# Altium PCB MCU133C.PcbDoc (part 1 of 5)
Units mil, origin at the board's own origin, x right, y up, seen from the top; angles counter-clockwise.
Board outline 2300 x 5500 mil, 4 copper layers (Top Signal, GND, PWR, Bottom Signal), stack 61.6 mil thick; 278 components, 226 nets, 1057 pads, 868 vias.
Unrouted connection lines stored in the file: 237.
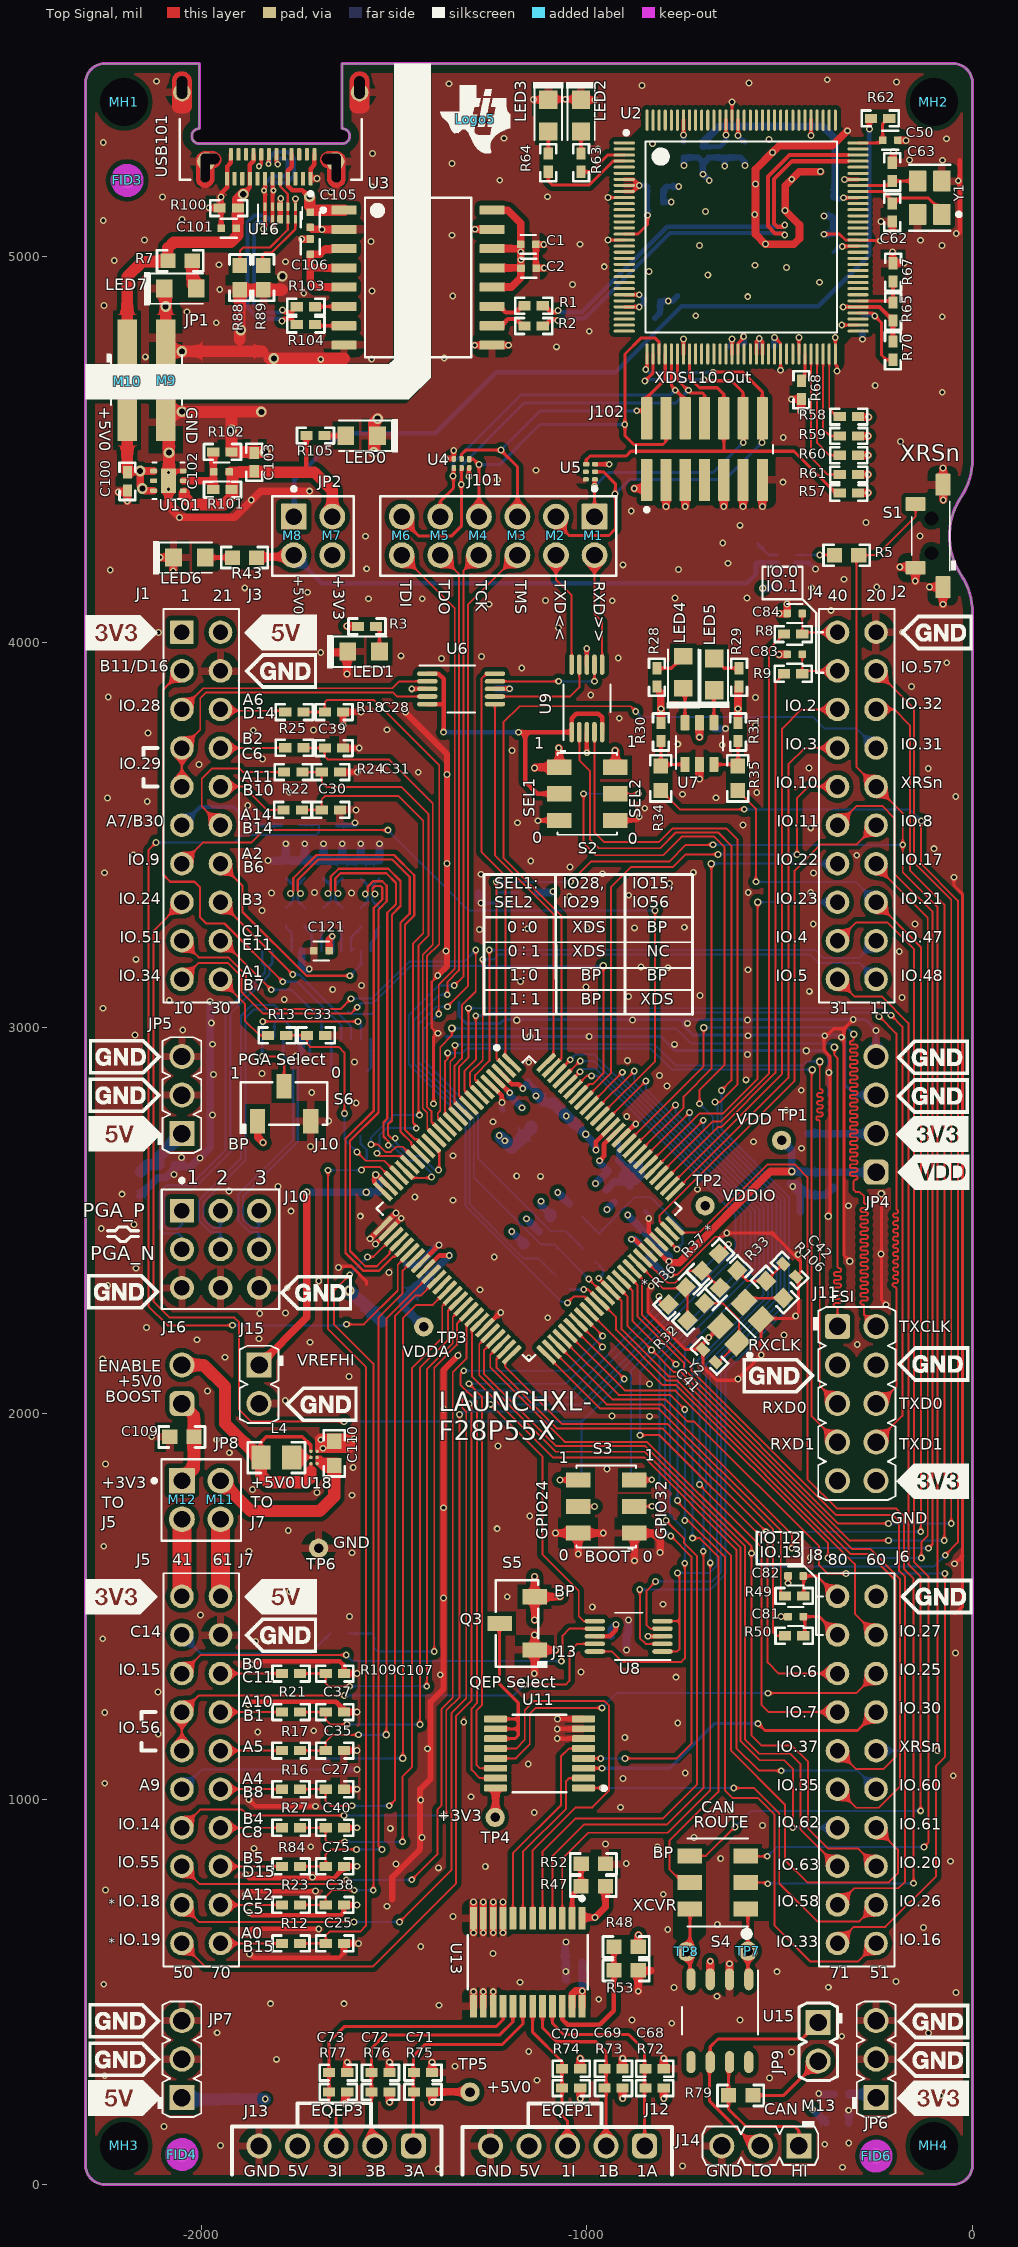
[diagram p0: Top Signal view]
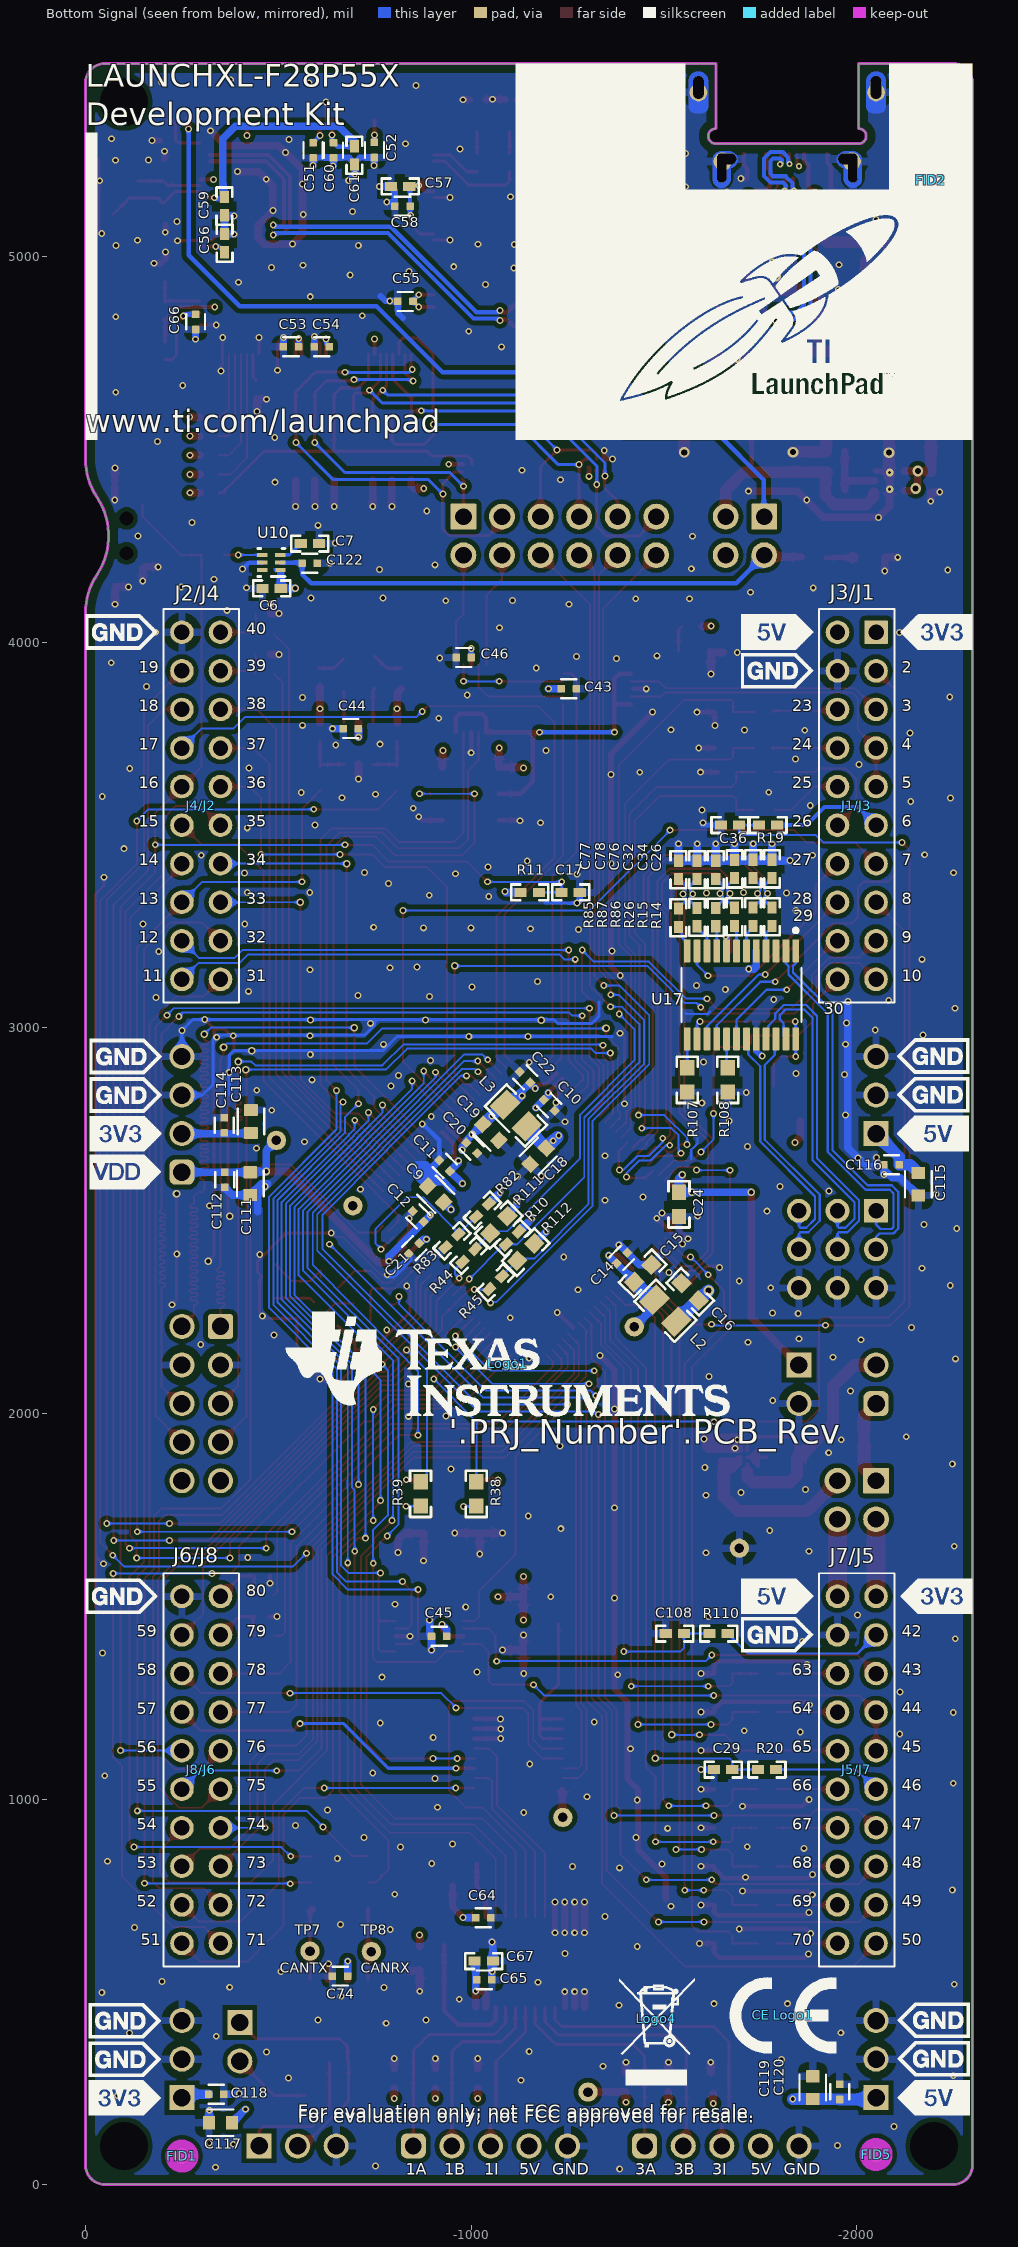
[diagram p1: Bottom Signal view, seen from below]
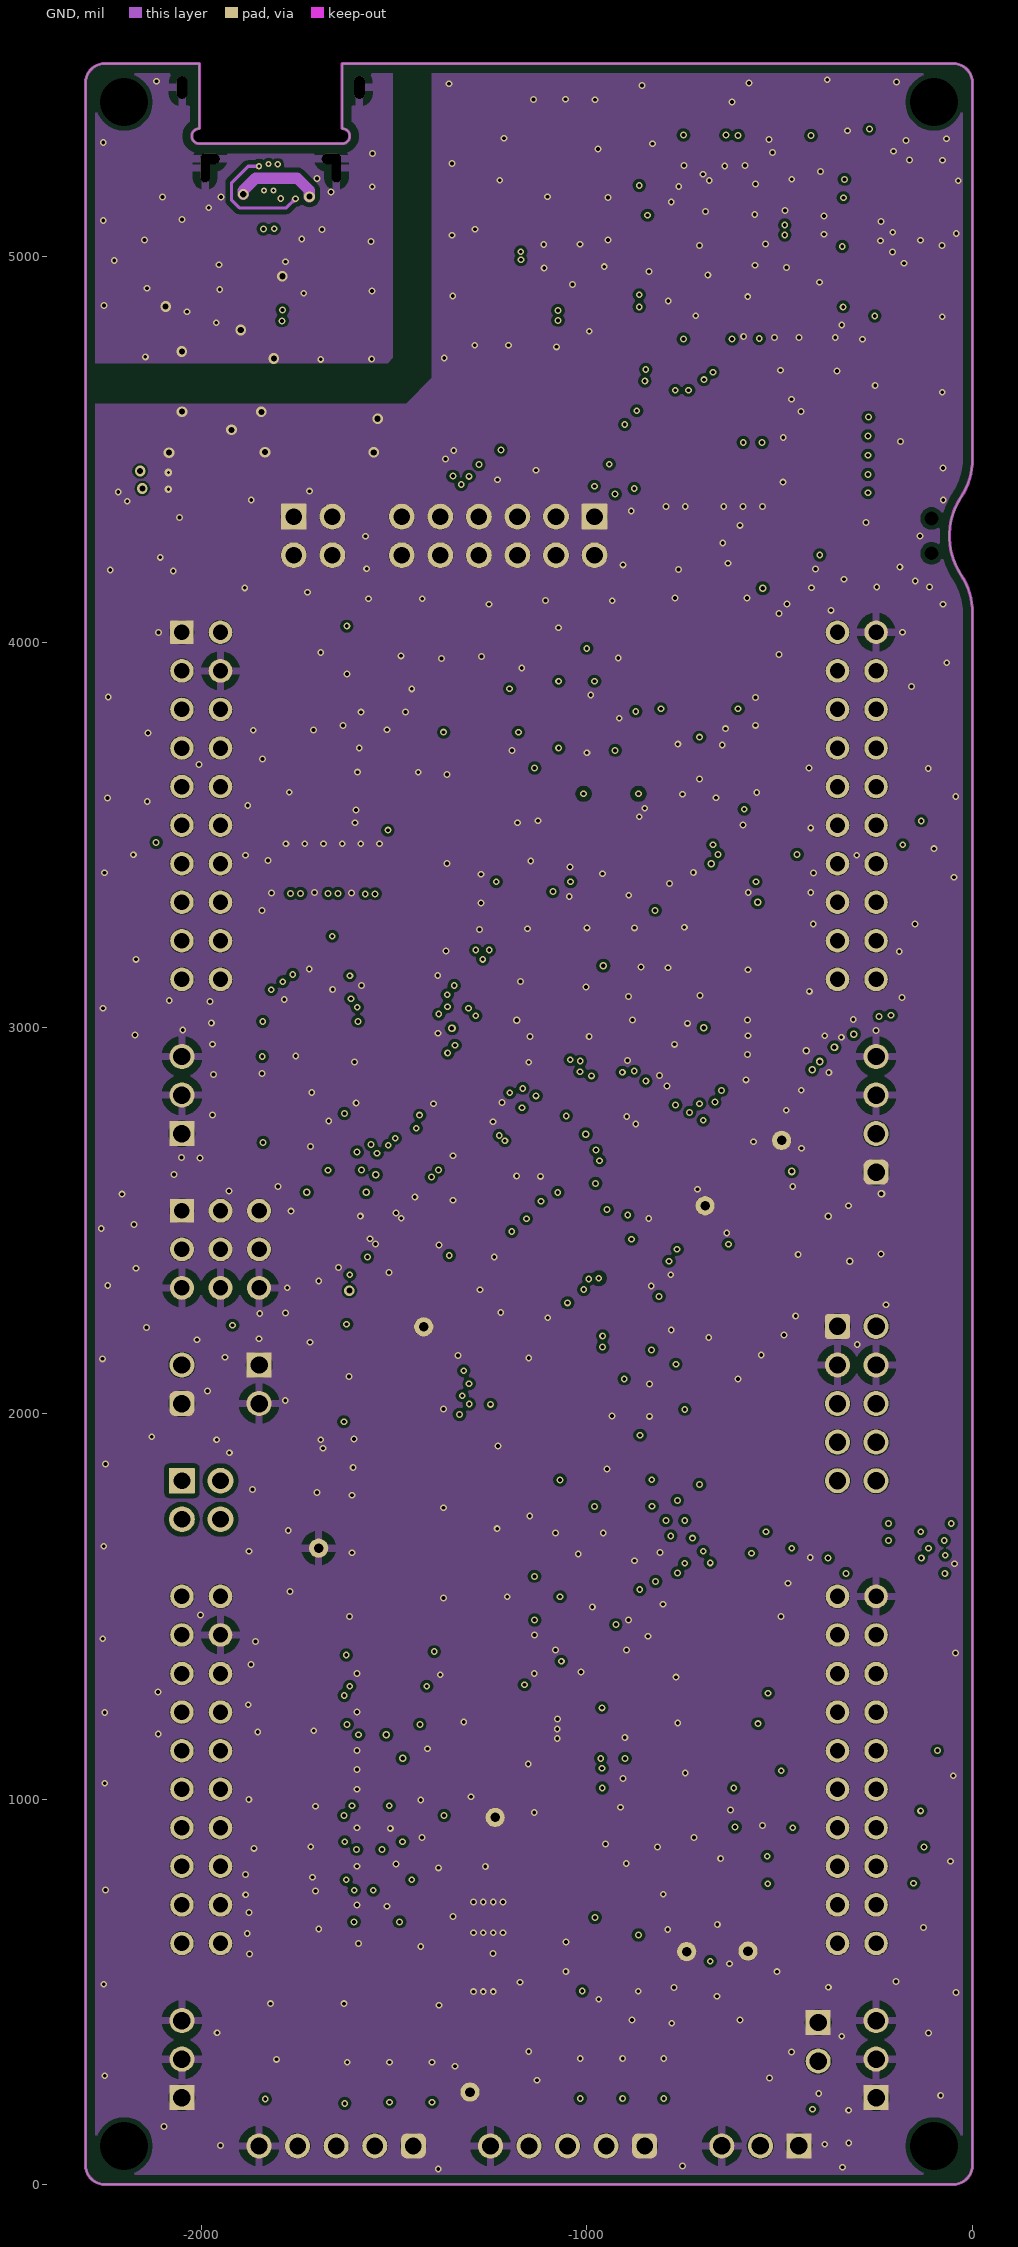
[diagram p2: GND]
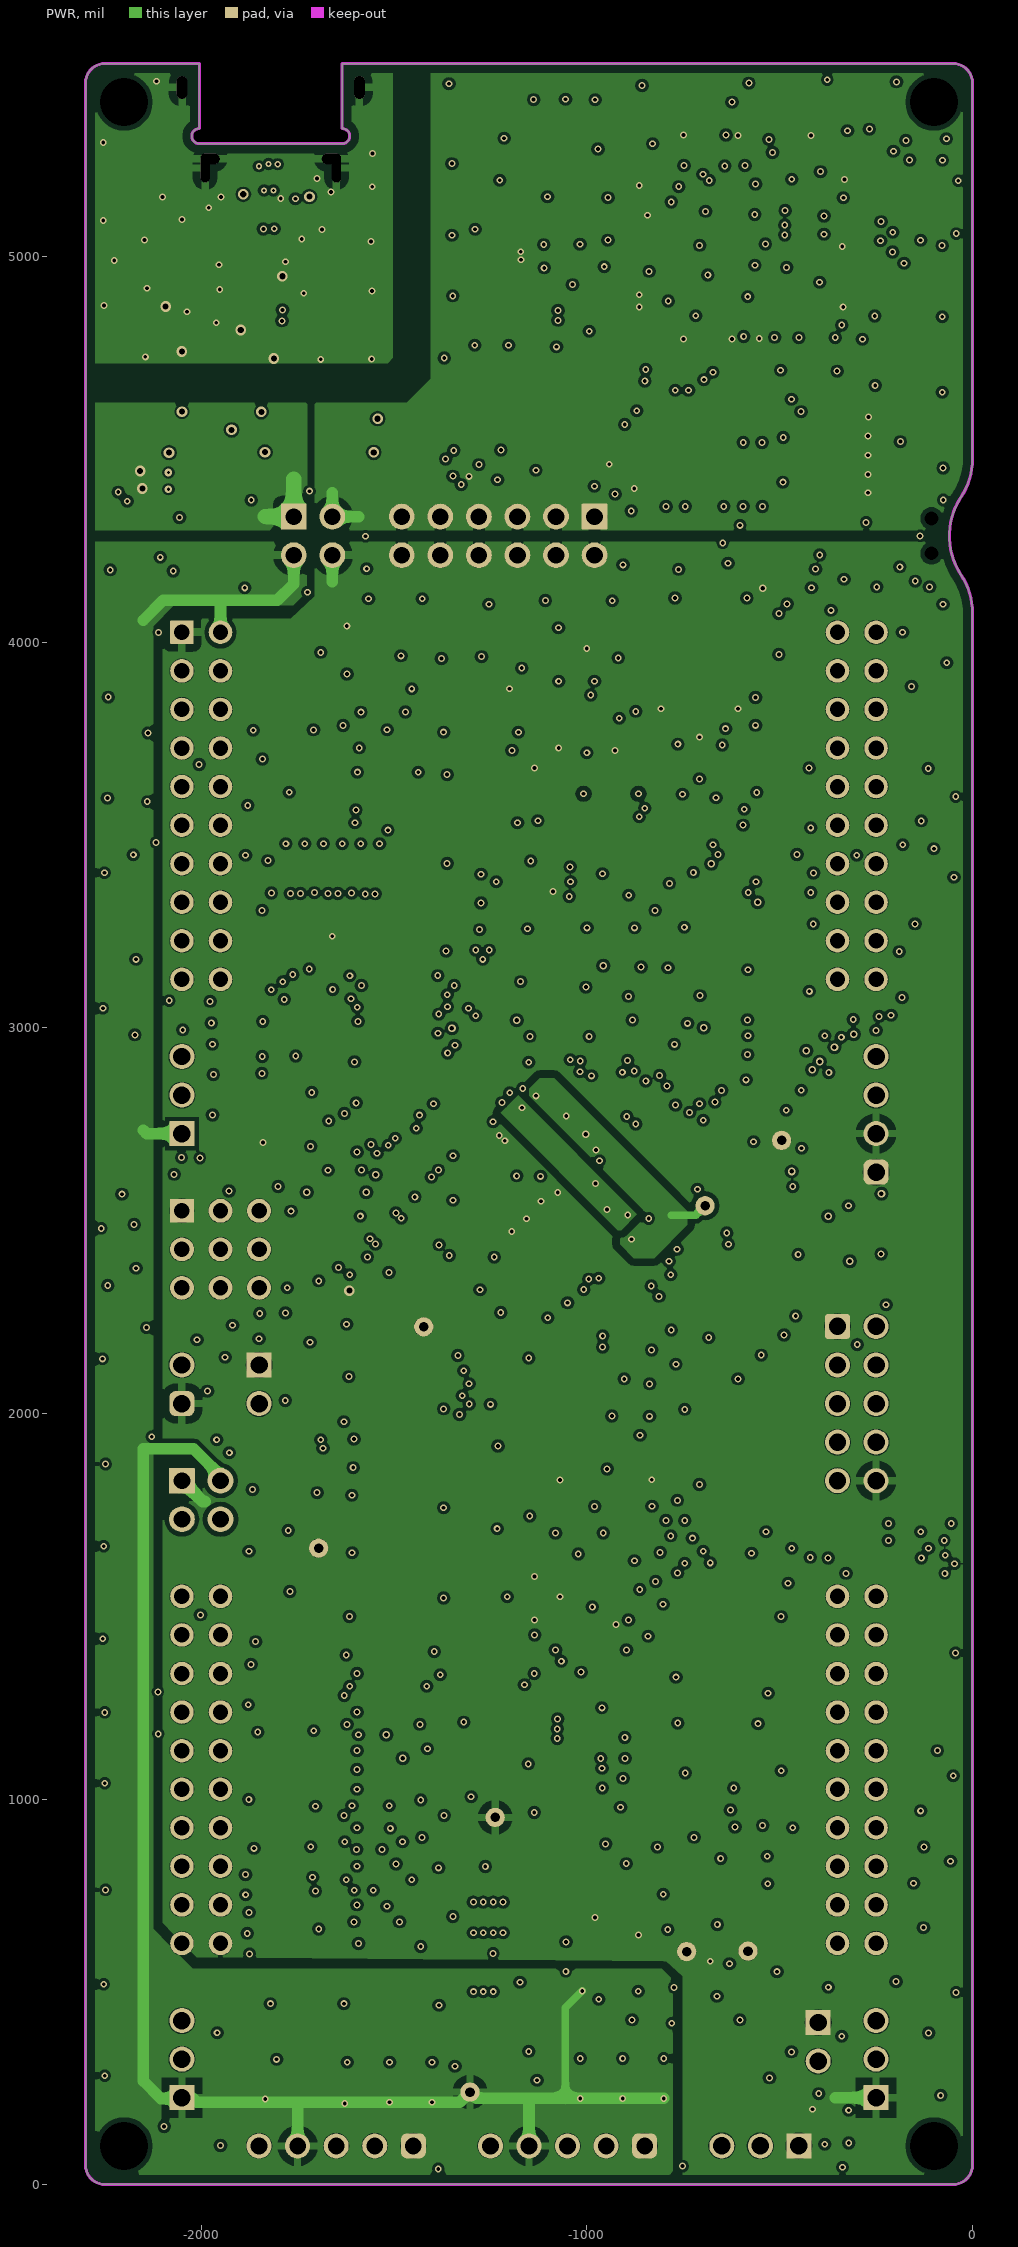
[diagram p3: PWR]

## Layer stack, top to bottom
Top Solder: solder mask 0.4, Solder Resist, Dk 3.5
Top Signal: signal copper 1.4
Dielectric 1: prepreg 8, FR-4, Dk 4.2
GND: signal copper 1.4
Dielectric 2: core 40, FR-4, Dk 4.2
PWR: signal copper 1.4
Dielectric 3: prepreg 8, FR-4, Dk 4.2
Bottom Signal: signal copper 1.4
Bottom Solder: solder mask 0.4, Solder Resist, Dk 3.5

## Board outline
-2250.04,0.55 cw(c-2250.04,50.55) -2300.04,50.55 -2300.04,5450.55 cw(c-2250.04,5450.55) -2250.04,5500.55 -2004.76,5500.55 -2004.76,5332.05 ccw(c-2004.76,5312.36) -2024.45,5312.36 ccw(c-2004.76,5312.36) -2004.76,5292.68 -1634.68,5292.68 ccw(c-1634.68,5312.36) -1615,5312.36 ccw(c-1634.68,5312.36) -1634.68,5332.05 -1634.68,5500.55 -50.04,5500.55 cw(c-50.04,5450.55) -0.04,5450.55 -0.04,4475.55 cw(c-181.7,4475.55) -30.04,4375.55 ccw(c121.63,4275.55) -30.04,4175.55 cw(c-181.7,4075.55) -0.04,4075.55 -0.04,50.55 cw(c-50.04,50.55) -50.04,0.55

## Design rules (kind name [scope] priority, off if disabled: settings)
AcuteAngle [All] p1: minimum=4.50000000000000E+0001 checktracksonly=TRUE
AssemblyTestPointUsage [All] p1: valid=2
BoardOutlineClearance BoardOutlineClearance_MountingHoles [OnCopper and InComponentClass('Mounting Holes')] p1: gap=40 ignorepadtopadclearanceinfootprint=FALSE
BoardOutlineClearance BoardOutlineClearance_Poly [OnCopper and IsPoly] p2: gap=25 ignorepadtopadclearanceinfootprint=FALSE
BoardOutlineClearance BoardOutlineClearance_USB101 [InComponent('USB101')] p3: gap=0 ignorepadtopadclearanceinfootprint=FALSE
BoardOutlineClearance [OnCopper and Not InComponentClass('Logo') and not InComponentClass('FiducialMark') and not InRegion(1000,500,4000,800) and not InPoly] p4: gap=10 ignorepadtopadclearanceinfootprint=FALSE
Clearance USB101 [InComponent('USB101') vs OnLayer('Keep-Out Layer')] p1: gap=7.87 ignorepadtopadclearanceinfootprint=FALSE
Clearance Clearance_1 [inpolygon vs inpolygon] p2: gap=19.68 ignorepadtopadclearanceinfootprint=FALSE
Clearance ISVIA [ISVIA vs ISVIA] p3: gap=7.87 ignorepadtopadclearanceinfootprint=FALSE
Clearance Clearance_FiducialMark [InComponentClass('FiducialMark') vs InComponentClass('FiducialMark')] p4: gap=0 ignorepadtopadclearanceinfootprint=FALSE
Clearance Clearance_Boardedge [All vs IsKeepOut] p5: gap=11.81 ignorepadtopadclearanceinfootprint=FALSE
Clearance INPOLYGON [InPolygon] p6: gap=11.81 ignorepadtopadclearanceinfootprint=FALSE
Clearance [All] p7: gap=5.91 ignorepadtopadclearanceinfootprint=FALSE
ComponentClearance ComponentClearance_THtoTH_1 [All vs InComponentClass('Shunt')] p1: gap=0 collisioncheckmode=3 verticalgap=0 showdistances=FALSE
ComponentClearance "ComponentClearance_overlay to overlay" [OnBottomSilkscreen vs OnTopSilkscreen] p2: gap=0 collisioncheckmode=3 verticalgap=0 showdistances=FALSE
ComponentClearance ComponentClearance_MountingHoles_FiducialMarks [InComponentClass('Mounting Holes') vs InComponentClass('FiducialMark')] p3: gap=50 collisioncheckmode=3 verticalgap=10 showdistances=FALSE
ComponentClearance ComponentClearance_Shunt [InComponentClass('Header') vs InComponentClass('Shunt')] p4: gap=0 collisioncheckmode=3 verticalgap=0 showdistances=FALSE
ComponentClearance ComponentClearance_Logo [InComponentClass('Logo')] p5: gap=0 collisioncheckmode=3 verticalgap=0 showdistances=FALSE
ComponentClearance ComponentClearance_Logo_1 [InComponentClass('Logo') vs InComponentClass('Logo')] p6: gap=0 collisioncheckmode=3 verticalgap=0 showdistances=FALSE
ComponentClearance ComponentClearance_ScrewToNut [(HasFootprint('NY PMS 440 0025 PH')) vs (HasFootprint('Keystone_1902C'))] p7: gap=3.94 collisioncheckmode=3 verticalgap=3.94 showdistances=FALSE
ComponentClearance ComponentClearance_MountingHoles [InComponentClass('Mounting Holes')] p8: gap=250 collisioncheckmode=3 verticalgap=100000 showdistances=FALSE
ComponentClearance ComponentClearance_SmallPassives [HasFootprint('0201*') or HasFootprint('0402*') or HasFootprint('0508') or HasFootprint('0603*') or HasFootprint('0612') or HasFootprint('0805*') or HasFootprint('0815*') or HasFootprint('0830*') or HasFootprint('1206*') or HasFootprint('1210*') or HasFootprint('1808*') or HasFootprint('1812*') or HasFootprint('1825*') or HasFootprint('2010*') or HasFootprint('2220*') or HasFootprint('2225*') or HasFootprint('2512*') or HasFootprint('2728*') or HasFootprint('3518*') vs HasFootprint('0201*') or HasFootprint('0402*') or HasFootprint('0508') or HasFootprint('0603*') or HasFootprint('0612') or HasFootprint('0805*') or HasFootprint('0815*') or HasFootprint('0830*') or HasFootprint('1206*') or HasFootprint('1210*') or HasFootprint('1808*') or HasFootprint('1812*') or HasFootprint('1825*') or HasFootprint('2010*') or HasFootprint('2220*') or HasFootprint('2225*') or HasFootprint('2512*') or HasFootprint('2728*') or HasFootprint('3518*')] p9: gap=10 collisioncheckmode=3 verticalgap=0 showdistances=FALSE
ComponentClearance ComponentClearance_THtoSMT [IsThruComponent vs IsSMTComponent] p10: gap=10 collisioncheckmode=3 verticalgap=10 showdistances=FALSE
ComponentClearance ComponentClearance_THtoTH [IsThruComponent vs IsThruComponent] p11: gap=20 collisioncheckmode=3 verticalgap=30 showdistances=FALSE
DiffPairsRouting [All] p1: maxlimit=100 minlimit=5.91 mostfreqgap=5.91 toplayer_minwidth=5.91 toplayer_maxwidth=15 toplayer_prefwidth=10.63 midlayer1_minwidth=5.91 midlayer1_maxwidth=15 midlayer1_prefwidth=10.63 midlayer2_minwidth=5.91 midlayer2_maxwidth=15 midlayer2_prefwidth=10.63 bottomlayer_minwidth=5.91 bottomlayer_maxwidth=15 bottomlayer_prefwidth=10.63 maxuncoupledlength=1000
FabricationTestPointUsage TestPointUsage [All] p1: valid=2 allowmultiple=FALSE
FabricationTestpoint Testpoint [All] p1: side=3 testpointundercomponent=TRUE minsize=40 maxsize=100 preferedsize=60 minholesize=0 maxholesize=40 preferedholesize=32 testpointgrid=1 allowsidetop=TRUE allowsidebottom=TRUE usegrid=TRUE gridtolerance=0.01
FanoutControl Fanout_LCC [IsLCC] p1: bgadir=Out bgaviamode=Centered fanoutstyle=Auto fanoutdirection=Alternating viagrid=1 // Fanout_LCC (Default Rule)
FanoutControl Fanout_BGA [IsBGA] p2: bgadir=Out bgaviamode=Centered fanoutstyle=Auto fanoutdirection=Alternating viagrid=1 // Fanout_BGA (Default Rule)
FanoutControl Fanout_Default [All] p4: bgadir=Out bgaviamode=Centered fanoutstyle=Auto fanoutdirection=Alternating viagrid=1 // Fanout_Default (Default Rule)
FanoutControl Fanout_Small [(CompPinCount < 5)] p5: bgadir=Out bgaviamode=Centered fanoutstyle=Auto fanoutdirection=OutThenIn viagrid=1 // Fanout_Small (Default Rule)
HoleSize [All] p1: absolutevalues=TRUE maxlimit=251 minlimit=7.87 maxpercent=80.000 minpercent=20.000
HoleToHoleClearance HoleToHoleClearance_USB101 [InComponent('USB101') vs InComponent('USB101')] p1: gap=0 allowstackedmicrovias=TRUE
HoleToHoleClearance [All] p2: gap=9.84 allowstackedmicrovias=TRUE
MatchedLengths FSIRX [InNetClass('FSIRX')] p1: tolerance=25 checknetsindiffpair=FALSE checkdiffpairvsdiffpair=TRUE checkxsignals=TRUE checkothers=TRUE
MatchedLengths FSITX [InNetClass('FSITX')] p2: tolerance=25 checknetsindiffpair=FALSE checkdiffpairvsdiffpair=TRUE checkxsignals=TRUE checkothers=TRUE
MinimumAnnularRing MinimumAnnularRing_1 [InComponent('USB101')] p1: minimumring=0
MinimumAnnularRing [All] p2: minimumring=3.94
MinimumAnnularRing MinimumAnnularRing_ThermalPadVias [IsVia and InAnyComponent] p3: minimumring=3.94
MinimumSolderMaskSliver MinimumSolderMaskSliver_Logo [InComponentClass('Logo') vs InComponentClass('Logo')] p1: minsoldermaskwidth=0.7
MinimumSolderMaskSliver [All] p2: minsoldermaskwidth=3
PlaneClearance [All] p1: clearance=5
PlaneConnect [All] p1: planeconnectstyle=Relief reliefexpansion=10 reliefentries=4 reliefconductorwidth=25 reliefairgap=10
PolygonConnect PolygonConnect_via [isvia] p1: connectstyle=Direct reliefconductorwidth=10 reliefentries=4 polygonreliefangle="90 Angle" airgapwidth=5
PolygonConnect [All] p2: connectstyle=Relief reliefconductorwidth=20 reliefentries=4 polygonreliefangle="90 Angle" airgapwidth=19.68
RoutingVias ThermalPadVias [IsVia and InAnyComponent] p1: holewidth=7.87 width=19.68 viastyle="Through Hole" minholewidth=7.87 minwidth=19.68 maxholewidth=12.99 maxwidth=23.62
RoutingVias [All] p2: holewidth=9.84 width=17.72 viastyle="Through Hole" minholewidth=7.87 minwidth=15.75 maxholewidth=40 maxwidth=65
SilkToBoardRegionClearance [Not ((IsComment or IsDesignator) And (Hide <> 'False')) and not InRegion(1000,500,4000,800)] p1:
SilkToSilkClearance SilkToSilkClearance_Pb-FreeLogo [(HasFootprint('Pb-Free_Overlay_Medium') OR HasFootprint('Pb-Free_Overlay_Small')) vs (HasFootprint('Pb-Free_Overlay_Medium') OR HasFootprint('Pb-Free_Overlay_Small'))] p1: silktosilkclearance=0
SilkToSilkClearance [All] p2: silktosilkclearance=3
SilkToSolderMaskClearance SilkToComponentPadClearance [(IsPad or IsFill or IsRegion) and InAnycomponent] p1: minsilkscreentomaskgap=3 clearancetoexposedcopper=TRUE
SilkToSolderMaskClearance "Silk to Solder Mask Opening" [(IsPad or IsFIll or IsRegion) and InAnyComponent] p2: minsilkscreentomaskgap=3 clearancetoexposedcopper=TRUE
SolderMaskExpansion SolderMaskExpansion_1 [All] p1: expansion=4 istentingtop=FALSE
SolderMaskExpansion SolderMaskExpansion_Via [IsVia] p2: expansion=2 istentingtop=FALSE
Width Analog [InNetClass('Analog')] p1: maxlimit=25 minlimit=8 preferedwidth=8
Width [All] p2: maxlimit=100 minlimit=5 preferedwidth=5 checkconnectedcopper=TRUE
13 further rules are at their usual default settings.

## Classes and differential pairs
component class MCU133C_F28P55x_Device: C9 C10 C11 C12 C14 C15 C16 C17 C18 C19 C20 C21 C22 L2 L3 R10 R11 R44 R45 R82 R83 R111 R112 S1
net class FSITX: GPIO44_FSITXCLK GPIO49_FSITXD0 GPIO50_FSITXD1
net class FSIRX: GPIO52_FSIRXD0 GPIO53_FSIRXD1 GPIO54_FSIRXCLK
component class MCU133C_USB_and_Power: C1 C2 C6 C7 C100 C101 C102 C103 C105 C106 C109 C110 C111 C112 C113 C114 C115 C116 C117 C118 C119 C120 C122 J16 JP1 JP2 JP4 JP5 JP6 JP7 JP10 L4 LED0 LED1 LED6 LED7 R1 R2 R3 R5 R7 R43 R88 R89 R100 R101 R102 R103 R104 R105 TP1 TP2 TP3 TP4 TP5 TP6 U3 U10 U16 U18 U101 USB101
component class MCU133C_XDS110_MCU: 45mil C50 C51 C52 C53 C54 C55 C56 C57 C58 C59 C60 C61 C62 C63 C66 J101 J102 LED2 LED3 R57 R58 R59 R60 R61 R62 R63 R64 R65 R67 R68 R70 R? U2 U4 U5 Y1
component class MCU133C_ADC: C24 C25 C26 C27 C28 C29 C30 C31 C32 C33 C34 C35 C36 C37 C38 C39 C40 C75 C76 C77 C78 C107 C108 J15 R12 R13 R14 R15 R16 R17 R18 R19 R20 R21 R22 R23 R24 R25 R26 R27 R84 R85 R86 R87 R109 R110 U1
component class MCU133C_Connectors: C68 C69 C70 C71 C72 C73 C74 C81 C82 C83 C84 J1/J3 J4/J2 J5/J7 J8/J6 J10 J11 J12 J13 J14 JP8 JP9 R8 R9 R49 R50 R72 R73 R74 R75 R76 R77 R79 TP7 TP8 U15
component class MCU133C_AltRouting_Misc: C41 C42 C43 C44 C45 C46 C64 C65 C67 C121 LED4 LED5 R28 R29 R30 R31 R32 R33 R34 R35 R36 R37 R38 R39 R47 R48 R52 R53 R106 R107 R108 S2 S3 S4 S5 S6 U6 U7 U8 U9 U11 U13 U17 Y2
component class Header: J11 J12 J13 J14 J15 J16 JP1 JP4 JP5 JP6 JP7 JP9 JP10
component class AssemblyNote: ZZ1 ZZ2 ZZ3
component class FiducialMark: FID1 FID2 FID3 FID4 FID5 FID6
component class MCU133C_Hardware: "CE Logo1" FID1 FID2 FID3 FID4 FID5 FID6 Logo1 Logo3 Logo4 Logo5 M1 M2 M3 M4 M5 M6 M7 M8 M9 M10 M11 M12 M13 MH1 MH2 MH3 MH4 ZZ1 ZZ2 ZZ3
component class Logo: Logo1 Logo5
component class Shunt: M1 M2 M3 M4 M5 M6 M7 M8 M9 M10 M11 M12 M13
differential pair XDS_D: +XDS_D_P -XDS_D_N
differential pair USB_D: +USB_D_P -USB_D_N
differential pair PGA3_IN: +PGA3_IN_P -PGA3_IN_N
differential pair PGA2_IN: +PGA2_IN_P -PGA2_IN_N
differential pair PGA1_IN: +PGA1_IN_P -PGA1_IN_N
differential pair MCU_PGA3_IN: +MCU_PGA3_IN_P -MCU_PGA3_IN_N
differential pair MCU_PGA2_IN: +MCU_PGA2_IN_P -MCU_PGA2_IN_N
differential pair MCU_PGA1_IN: +MCU_PGA1_IN_P -MCU_PGA1_IN_N
differential pair ADCINPGA3_IN: +ADCINPGA3_IN_P -ADCINPGA3_IN_N
differential pair ADCINPGA2_IN: +ADCINPGA2_IN_P -ADCINPGA2_IN_N
differential pair ADCINPGA1_IN: +ADCINPGA1_IN_P -ADCINPGA1_IN_N

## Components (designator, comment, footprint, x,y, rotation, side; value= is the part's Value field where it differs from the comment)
C1 "885012205018" FP-885012205018_0402-MFG -1152.04,5031.55 r180 top value=100nF
C2 "885012205018" FP-885012205018_0402-MFG -1151.02,4969.92 r180 top value=100nF
C6 "885012205037" 0402 -482.76,4139.55 r0 bottom value=0.1uF
C7 "885012205037" 0402 -581.66,4255.55 r180 bottom value=0.1uF
C9 "CC0603KRX5R6BB106" FP-CC0603KRX5R6BB106_0603-MFG -907.86,2568.67 r225 bottom value=10µF
C10 "885012205018" FP-885012205018_0402-MFG -1202.71,2799.05 r45 bottom value=100nF
C11 "885012205018" FP-885012205018_0402-MFG -931.24,2642.53 r225 bottom value=100nF
C12 "885012205018" FP-885012205018_0402-MFG -862.62,2510.8 r225 bottom value=100nF
C14 "885012205018" FP-885012205018_0402-MFG -1391.08,2403 r315 bottom value=100nF
C15 "CGA3E3X5R1A225K080AB" 0603 -1445.2,2363.22 r135 bottom value=2.2uF
C16 "CGA3E3X5R1A225K080AB" 0603 -1567.88,2315.53 r45 bottom value=2.2uF
C17 "885012205037" 0402 -1258.04,3350.95 r180 bottom value=0.1uF
C18 "CC0603KRX5R6BB106" FP-CC0603KRX5R6BB106_0603-MFG -1173.78,2667.08 r135 bottom value=10µF
C19 "CC0603KRX5R6BB106" FP-CC0603KRX5R6BB106_0603-MFG -1051.11,2729.05 r45 bottom value=10µF
C20 "885012205018" FP-885012205018_0402-MFG -1001.61,2688.55 r45 bottom value=100nF
C21 "885012205018" FP-885012205018_0402-MFG -852.04,2427.95 r135 bottom value=100nF
C22 "885012205018" FP-885012205018_0402-MFG -1139.8,2871.97 r225 bottom value=100nF
C24 "CGA3E3X5R1A225K080AB" 0603 -1539.04,2542.09 r270 bottom value=2.2uF
C25 "GRM1555C1H331JA01D" 0402 -1653.66,625.55 r0 top value=330pF
C26 "GRM1555C1H331JA01D" 0402 -1779.95,3412.05 r90 bottom value=330pF
C27 "GRM1555C1H331JA01D" 0402 -1653.66,1025.55 r0 top value=330pF
C28 "GRM1555C1H331JA01D" 0402 -1655.67,3818.85 r0 top value=330pF
C29 "GRM1555C1H331JA01D" 0402 -1653.66,1076.55 r0 bottom value=330pF
C30 "GRM1555C1H331JA01D" 0402 -1663.82,3564.92 r0 top value=330pF
C31 "GRM1555C1H331JA01D" 0402 -1663.82,3662.93 r0 top value=330pF
C32 "GRM1555C1H331JA01D" 0402 -1683.26,3411.97 r90 bottom value=330pF
C33 "GRM1555C1H331JA01D" 0402 -1702.04,2980.24 r0 top value=330pF
C34 "GRM1555C1H331JA01D" 0402 -1731.34,3412.14 r90 bottom value=330pF
C35 "GRM1555C1H331JA01D" 0402 -1653.66,1125.55 r0 top value=330pF
C36 "GRM1555C1H331JA01D" 0402 -1671.42,3525.55 r0 bottom value=330pF
C37 "GRM1555C1H331JA01D" 0402 -1653.66,1225.55 r0 top value=330pF
C38 "GRM1555C1H331JA01D" 0402 -1653.66,725.55 r0 top value=330pF
C39 "GRM1555C1H331JA01D" 0402 -1655.75,3725.55 r0 top value=330pF
C40 "GRM1555C1H331JA01D" 0402 -1653.66,925.55 r0 top value=330pF
C41 "C0402C120J3GACAUTO" 0402 -682.4,2149.43 r135 top value=12pF
C42 "C0402C120J3GACAUTO" 0402 -474.04,2371.03 r315 top value=12pF
C43 "885012205018" FP-885012205018_0402-MFG -1253.39,3879.33 r180 bottom value=100nF
C44 "885012205018" FP-885012205018_0402-MFG -688.04,3776.02 r180 bottom value=100nF
C45 "885012205018" FP-885012205018_0402-MFG -916.78,1422.07 r0 bottom value=100nF
C46 "885012205018" FP-885012205018_0402-MFG -980.59,3960.28 r180 bottom value=100nF
C50 "885012205050" FP-885012205050_0402-MFG -213.15,5301.77 r180 top value=10nF
C51 "885012205050" FP-885012205050_0402-MFG -590.04,5275.55 r90 bottom value=10nF
C52 "885012205050" FP-885012205050_0402-MFG -749.25,5276.46 r90 bottom value=10nF
C53 "885012205050" FP-885012205050_0402-MFG -532.76,4765.83 r180 bottom value=10nF
C54 "885012205018" FP-885012205018_0402-MFG -612.68,4765.83 r180 bottom value=100nF
C55 "885012205018" FP-885012205018_0402-MFG -829.61,4883.66 r180 bottom value=100nF
C56 "885012105012" 0402 -360.83,5034.69 r90 bottom value=1uF
C57 "885012105012" 0402 -816.06,5181.97 r0 bottom value=1uF
C58 "885012205050" FP-885012205050_0402-MFG -822.04,5130.55 r180 bottom value=10nF
C59 "885012105012" 0402 -360,5130.83 r270 bottom value=1uF
C60 "885012205018" FP-885012205018_0402-MFG -643.19,5275.47 r90 bottom value=100nF
C61 "885012105012" 0402 -697.43,5262.48 r270 bottom value=1uF
C62 "CL05C120JB5NNNC" 0402 -207.94,5114.17 r270 top value=12pF
C63 "CL05C120JB5NNNC" 0402 -207.94,5219.53 r90 top value=12pF
C64 "885012205018" FP-885012205018_0402-MFG -1031.5,692.05 r180 bottom value=100nF
C65 "885012205018" FP-885012205018_0402-MFG -1034.29,531.06 r0 bottom value=100nF
C66 "885012205018" FP-885012205018_0402-MFG -285.51,4830.59 r90 bottom value=100nF
C67 "885012205061" 0402 -1032.64,579.72 r180 bottom value=1000pF
C68 "885012205061" 0402 -824.06,300.55 r0 top value=1000pF
C69 "885012205061" 0402 -930.79,300.55 r0 top value=1000pF
C70 "885012205061" 0402 -1040.79,300.55 r0 top value=1000pF
C71 "885012205061" 0402 -1425.04,290.55 r0 top value=1000pF
C72 "885012205061" 0402 -1535.04,290.55 r0 top value=1000pF
C73 "885012205061" 0402 -1645.04,290.55 r0 top value=1000pF
C74 "885012205018" FP-885012205018_0402-MFG -660.04,540.88 r0 bottom value=100nF
C75 "GRM1555C1H331JA01D" 0402 -1653.66,825.55 r0 top value=330pF
C76 "GRM1555C1H331JA01D" 0402 -1634.34,3409.63 r90 bottom value=330pF
C77 "GRM1555C1H331JA01D" 0402 -1537.7,3409.63 r90 bottom value=330pF
C78 "GRM1555C1H331JA01D" 0402 -1586.18,3409.63 r90 bottom value=330pF
C81 "885012205018" FP-885012205018_0402-MFG -458.62,1473.19 r0 top value=100nF
C82 "885012205018" FP-885012205018_0402-MFG -458.6,1578.5 r0 top value=100nF
C83 "885012205018" FP-885012205018_0402-MFG -461.02,3968.43 r0 top value=100nF
C84 "885012205018" FP-885012205018_0402-MFG -461.02,4074.49 r0 top value=100nF
C100 "885012105012" 0402 -2191.3,4416.93 r270 top value=1uF
C101 "885012205064" FP-885012205064_0402-MFG -1928.74,5073.35 r0 top value=3.3nF
C102 "885012205050" FP-885012205050_0402-MFG -1947.36,4441.5 r0 top value=10nF
C103 "885012105012" 0402 -1862.64,4466.93 r90 top value=1uF
C105 "885012205018" FP-885012205018_0402-MFG -1717.6,5095.55 r90 top value=100nF
C106 "885012205018" FP-885012205018_0402-MFG -1717.6,5025.87 r270 top value=100nF
C107 "GRM1555C1H331JA01D" 0402 -1653.66,1325.55 r0 top value=330pF
C108 "GRM1555C1H331JA01D" 0402 -1528.16,1429.3 r0 bottom value=330pF
C109 "885012106018" 0603 -2050.2,1939.12 r180 top value=2.2uF
C110 "GRM188R61C106KAALD" 0603 -1655.02,1896.25 r90 top value=10uF
C111 "CC0603KRX5R6BB106" FP-CC0603KRX5R6BB106_0603-MFG -427.54,2595.9 r90 bottom value=10µF
C112 "885012205018" FP-885012205018_0402-MFG -361.04,2605.87 r90 bottom value=100nF
C113 "CC0603KRX5R6BB106" FP-CC0603KRX5R6BB106_0603-MFG -429.04,2757.05 r270 bottom value=10µF
C114 "885012205018" FP-885012205018_0402-MFG -359.63,2747.05 r90 bottom value=100nF
C115 "CC0603KRX5R6BB106" FP-CC0603KRX5R6BB106_0603-MFG -2159.77,2594.39 r90 bottom value=10µF
C116 "885012205018" FP-885012205018_0402-MFG -2090.04,2644.55 r0 bottom value=100nF
C117 "CC0603KRX5R6BB106" FP-CC0603KRX5R6BB106_0603-MFG -350.04,160.55 r180 bottom value=10µF
C118 "885012205018" FP-885012205018_0402-MFG -339.02,234.55 r180 bottom value=100nF
C119 "CC0603KRX5R6BB106" FP-CC0603KRX5R6BB106_0603-MFG -1886.04,251.55 r270 bottom value=10µF
C120 "885012205018" FP-885012205018_0402-MFG -1956.04,240.55 r90 bottom value=100nF
C121 "885012205018" FP-885012205018_0402-MFG -1688.21,3199.32 r180 top value=100nF
C122 "885012205018" FP-885012205018_0402-MFG -581.22,4204.55 r180 bottom value=100nF
"CE Logo1" "CE Mark" CE_Mark_5mm -1808.54,439.05 r180 bottom
FID1 "Fiducial" Fiducial10-20 -250.04,74.24 r180 bottom
FID2 "Fiducial" Fiducial10-20 -2192.17,5197.43 r180 bottom
FID3 "Fiducial" Fiducial10-20 -2192.17,5197.43 r0 top
FID4 "Fiducial" Fiducial10-20 -2050.04,78.21 r0 top
FID5 "Fiducial" Fiducial10-20 -2050.04,78.21 r180 bottom
FID6 "Fiducial" Fiducial10-20 -250.04,74.24 r0 top
J1/J3 "SSQ-110-03-T-D" BoosterPack_40pin_J1J3 -2000.04,3575.55 r180 bottom locked
J4/J2 "SSQ-110-03-T-D" BoosterPack_40pin_J2J4 -300.04,3575.55 r180 bottom locked
J5/J7 "SSQ-110-03-T-D" BoosterPack_40pin_J5J7 -2000.04,1075.55 r180 bottom locked
J8/J6 "SSQ-110-03-T-D" BoosterPack_40pin_J6J8 -300.04,1075.55 r180 bottom locked
J10 "TSW-103-07-G-T" FP-TSW-103-07-G-T_HDR9-MFG -1950.04,2425.55 r270 top locked
J11 "61301021121" WURTH_61301021121 -300.04,2025.55 r270 top locked
J12 "61300511121" Wurth_61300511121 -1050.04,100.55 r180 top locked
J13 "61300511121" Wurth_61300511121 -1650.04,100.55 r180 top locked
J14 "61300311121" WURTH_61300311121 -550.04,100.55 r180 top locked
J15 "61300211121" WURTH_61300211121#1 -1850.04,2075.55 r270 top locked
J16 "61300211121" WURTH_61300211121#2 -2050.04,2075.55 r90 top locked
J101 "61301221121" FP-61301221121_HDR12-MFG -1230.04,4275.55 r180 top locked
J102 "FTSH-107-01-F-DV-K" FP-FTSH-107-01-F-DV-K_HDR14-MFG -694.84,4500.55 r0 top
JP1 "TSM-102-01-L-DV" Samtec_TSM-102-01-x-DV -2142.01,4679.55 r270 top locked
JP2 "61300421121" FP-61300421121_HDR4-MFG#1 -1710.04,4275.55 r0 top
JP4 "61300411121" WURTH_61300411121 -250.04,2775.55 r90 top locked
JP5 "61300311121" WURTH_61300311121 -2050.04,2825.55 r90 top locked
JP6 "61300311121" WURTH_61300311121 -250.04,325.55 r90 top locked
JP7 "61300311121" WURTH_61300311121 -2050.04,325.55 r90 top locked
JP8 "61300421121" FP-61300421121_HDR4-MFG#2 -2000.04,1775.55 r270 top locked
JP9 "61300211121" WURTH_61300211121#1 -400.04,370.55 r270 top
L2 "742792063" 0805_HV -1503.66,2266.26 r45 bottom value="60 ohm"
L3 "742792022" 0805_HV -1116.04,2772.55 r45 bottom value="220 ohm"
L4 "LQM21PN1R0MC0D" 0805_HV -1805.04,1885.55 r0 top value=1uH
LED0 "150080SS75000" WL-SMCW_RED_0805 -1584.04,4535.55 r180 top value=Red
LED1 "150080SS75000" WL-SMCW_RED_0805 -1579.02,3975.55 r0 top value=Red
LED2 "LTST-C170TBKT" LTST-C170TBKT_Blue -1015.04,5365.55 r90 top value=Blue
LED3 "LTST-C170TBKT" LTST-C170TBKT_Blue -1100.04,5365.55 r90 top value=Blue
LED4 "150080SS75000" WL-SMCW_RED_0805 -750.04,3921.89 r90 top value=Red
LED5 "LTST-C171GKT" LED_LTST-C171 -669.41,3916.46 r270 top value=Green
LED6 "150080SS75000" WL-SMCW_RED_0805 -2030.55,4219.33 r0 top value=Red
LED7 "150080SS75000" WL-SMCW_RED_0805 -2054.53,4916.93 r0 top value=Red
Logo1 "Texas Instruments" TI_Stacked_Overlay_Medium -1094.66,2128.71 r180 bottom
Logo3 "FCC disclaimer" FCC_disclaimer 994.96,160.55 r180 bottom
Logo4 "WEEE logo" WEEE_Minimum -1480.04,430.55 r180 bottom
Logo5 "Texas Instruments" TI_Symbol_Overlay_Small -1289.21,5355.55 r0 top
M1 "60900213421" Wurth_60900213421 -982.2,4275.55 r270 top
M2 "60900213421" Wurth_60900213421 -1080.39,4275.55 r90 top
M3 "60900213421" Wurth_60900213421 -1180.04,4275.55 r90 top
M4 "60900213421" Wurth_60900213421 -1280.04,4275.55 r90 top
M5 "60900213421" Wurth_60900213421 -1380.04,4275.55 r90 top
M6 "60900213421" Wurth_60900213421 -1480.04,4275.55 r90 top
M7 "60900213421" Wurth_60900213421 -1660.04,4275.55 r90 top
M8 "60900213421" Wurth_60900213421 -1763.29,4275.57 r90 top
M9 "60900213421" Wurth_60900213421 -2090,4677.4 r90 top
M10 "60900213421" Wurth_60900213421 -2191.93,4675.55 r90 top
M11 "60900213421" Wurth_60900213421 -1950.04,1775.55 r90 top
M12 "60900213421" Wurth_60900213421 -2049.65,1775.55 r90 top
M13 "60900213421" Wurth_60900213421 -399.14,371.85 r90 top
MH1 "MTG_NoPads" NPTH125mil -2200.04,5400.55 r0 top
MH2 "MTG_NoPads" NPTH125mil -100.04,5400.55 r0 top
MH3 "MTG_NoPads" NPTH125mil -2200.04,100.55 r0 top
MH4 "MTG_NoPads" NPTH125mil -100.04,100.55 r0 top locked
R1 "RC0402JR-070RL" 0402 -1137.91,4872.4 r0 top value=0
R2 "RC0402JR-070RL" 0402 -1137.91,4819.92 r0 top value=0
R3 "CRCW0402680RJNED" 0402 -1570.28,4041.14 r180 top value=680
R5 "ERJ-3GEY0R00V" 0603 -326.22,4225.55 r180 top value=0
R7 "RC0603JR-073KL" 0603 -2054.84,4988.9 r180 top value=3.0k
R8 "RC0402JR-070RL" 0402 -465.08,4021.02 r0 top value=0
R9 "RC0402JR-070RL" 0402 -465.08,3918.27 r0 top value=0
R10 "CRCW04022K20JNED" 0402 -1107.19,2454.99 r135 bottom value=2.2k
R11 "CRCW04022K20JNED" 0402 -1151.97,3350.95 r0 bottom value=2.2k
R12 "RC0402JR-070RL" 0402 -1767.31,625.55 r0 top value=0
R13 "RC0402JR-070RL" 0402 -1803.22,2980.24 r0 top value=0
R14 "RC0402JR-070RL" 0402 -1779.76,3287.97 r90 bottom value=0
R15 "RC0402JR-070RL" 0402 -1731.26,3287.97 r90 bottom value=0
R16 "RC0402JR-070RL" 0402 -1767.31,1025.55 r0 top value=0
R17 "RC0402JR-070RL" 0402 -1767.31,1125.55 r0 top value=0
R18 "RC0402JR-070RL" 0402 -1758.66,3818.85 r0 top value=0
R19 "RC0402JR-070RL" 0402 -1769.83,3525.55 r0 bottom value=0
R20 "RC0402JR-070RL" 0402 -1767.31,1076.55 r0 bottom value=0
R21 "RC0402JR-070RL" 0402 -1767.31,1225.55 r0 top value=0
R22 "RC0402JR-070RL" 0402 -1762.63,3564.92 r0 top value=0
R23 "RC0402JR-070RL" 0402 -1767.31,725.55 r0 top value=0
R24 "RC0402JR-070RL" 0402 -1761.31,3662.93 r0 top value=0
R25 "RC0402JR-070RL" 0402 -1758.42,3726.18 r0 top value=0
R26 "RC0402JR-070RL" 0402 -1682.46,3287.71 r90 bottom value=0
R27 "RC0402JR-070RL" 0402 -1767.31,925.55 r0 top value=0
R28 "CRCW0402680RJNED" 0402 -818.19,3908.86 r270 top value=680
R29 "CRCW0402680RJNED" 0402 -605.04,3908.86 r270 top value=680
R30 "CRCW040210M0JNED" 0402 -808,3767.08 r90 top value=10Meg
R31 "CRCW040210M0JNED" 0402 -608,3767.08 r90 top value=10Meg
R32 "CRCW06030000Z0EA" 0603 -716.86,2263.21 r45 top value=0
R33 "CRCW06030000Z0EA" 0603 -632.54,2348.2 r45 top value=0
R34 "CRCW06030000Z0EA" 0603 -808,3647.08 r90 top value=0
R35 "CRCW06030000Z0EA" 0603 -609,3647.08 r90 top value=0
R36 "CRCW06030000Z0EA" 0603 -765.88,2304.95 r45 top value=0
R37 "CRCW06030000Z0EA" 0603 -679.49,2392.09 r225 top value=0
R38 "RC0603FR-0710KL" 0603 -1013.54,1791.22 r270 bottom value=10.0k
R39 "RC0603FR-0710KL" 0603 -868.82,1791.22 r90 bottom value=10.0k
R43 "RC0603JR-073KL" 0603 -1887.8,4219.33 r0 top value=3.0k
R44 "RC0402JR-070RL" 0402 -994.18,2409.69 r135 bottom value=0
R45 "RC0402JR-070RL" 0402 -1063.71,2339.01 r135 bottom value=0
R47 "CRCW06030000Z0EA" 0603 -983.43,774.29 r0 top value=0
R48 "CRCW06032K20JNEA" 0603 -898.29,616.5 r0 top value=2.2k
R49 "RC0402JR-070RL" 0402 -462.56,1526.81 r0 top value=0
R50 "RC0402JR-070RL" 0402 -462.56,1423.5 r0 top value=0
R52 "CRCW06030000Z0EA" 0603 -982.91,831.81 r180 top value=0
R53 "CRCW06030000Z0EA" 0603 -898.29,555.55 r0 top value=0
R57 "CRCW04023K30JNED" 0402 -320.59,4387.32 r0 top value=3.3k
R58 "CRCW04021K00FKED" 0402 -320.75,4584.72 r0 top value=1.00k
R59 "CRCW04021K00FKED" 0402 -320.75,4534.72 r0 top value=1.00k
R60 "CRCW04021K00FKED" 0402 -320.75,4484.72 r0 top value=1.00k
R61 "CRCW04021K00FKED" 0402 -320.75,4434.72 r0 top value=1.00k
R62 "CRCW0402100RJNED" 0402 -239.33,5358.46 r0 top value=100
R63 "RC0402FR-07470RL" 0402 -1015.04,5243.54 r270 top value=470
R64 "RC0402FR-07470RL" 0402 -1100.04,5243.54 r270 top value=470
R65 "CRCW040210K0JNED" 0402 -206.02,4857.64 r270 top value=10k
R67 "CRCW040210K0JNED" 0402 -206.02,4959.17 r270 top value=10k
R68 "CRCW04024K87FKED" 0402 -443.43,4654.45 r90 top value=4.87k
R70 "CRCW040251R0JNED" 0402 -206.38,4756.14 r90 top value=51
R72 "CRCW04021K00FKED" 0402 -824.06,250.55 r0 top value=1.00k
R73 "CRCW04021K00FKED" 0402 -930.79,250.55 r0 top value=1.00k
R74 "CRCW04021K00FKED" 0402 -1040.79,250.55 r0 top value=1.00k
R75 "CRCW04021K00FKED" 0402 -1425.04,240.55 r0 top value=1.00k
R76 "CRCW04021K00FKED" 0402 -1535.04,240.55 r0 top value=1.00k
R77 "CRCW04021K00FKED" 0402 -1645.04,240.55 r0 top value=1.00k
R79 "RC0603FR-07120RL" 0603 -601.04,231.55 r180 top value=120
R82 "ERJ-2GE0R00X" 0402 -1029.26,2526.92 r315 bottom value=0
R83 "ERJ-2GE0R00X" 0402 -950.22,2447.72 r315 bottom value=0
R84 "RC0402JR-070RL" 0402 -1767.31,825.55 r0 top value=0
R85 "RC0402JR-070RL" 0402 -1537.7,3285.4 r90 bottom value=0
R86 "RC0402JR-070RL" 0402 -1634.34,3286.8 r90 bottom value=0
R87 "RC0402JR-070RL" 0402 -1586.18,3286.8 r90 bottom value=0
R88 "RC0603JR-075K1L" 0603 -1899.66,4945.43 r90 top value=5.1k
R89 "RC0603JR-075K1L" 0603 -1838.7,4945.43 r90 top value=5.1k
R100 "CRCW04021M00FKED" 0402 -1928.66,5125.55 r0 top value=1.00Meg
R101 "CRCW040252K3FKED" 0402 -1945.04,4395.55 r0 top value=52.3k
R102 "CRCW040230K0FKED" 0402 -1945.04,4493.55 r180 top value=30.0k
R103 "RC0402JR-070RL" 0402 -1728.58,4869.76 r0 top value=0
R104 "RC0402JR-070RL" 0402 -1728.58,4823.43 r0 top value=0
R105 "CRCW0402680RJNED" 0402 -1703.66,4535.55 r180 top value=680
R106 "FC0603E50R0BTBST1" 0603 -512.79,2321.34 r135 top value=50
R107 "CRCW06030000Z0EA" 0603 -1560.26,2864.92 r270 bottom value=0
R108 "CRCW06030000Z0EA" 0603 -1665.19,2864.92 r270 bottom value=0
R109 "RC0402JR-070RL" 0402 -1767.31,1325.55 r0 top value=0
R110 "RC0402JR-070RL" 0402 -1641.81,1429.3 r0 bottom value=0
R111 "RC0603FR-0710KL" 0603 -1071.75,2489.21 r135 bottom value=10.0k
R112 "RC0603FR-0710KL" 0603 -1141.61,2418.2 r135 bottom value=10.0k
S1 "1188E-1K2-V-TR" SW_1188E -120.04,4275.55 r180 top
S2 "CAS-D20TA" SW_CAS-D20TA -998.98,3606.87 r0 top
S3 "CAS-D20TA" SW_CAS-D20TA -949.76,1758.5 r180 top
S4 "CAS-220TA" SW_CAS-220TA -660.71,783.58 r180 top locked
S5 "CAS-120TA" SW_CAS-120TA -1180.71,1455.6 r180 top
S6 "CAS-120TA" SW_CAS-120TA -1785.04,2803.28 r90 top
TP1 "TESTPOINT" TP_50MIL-25MILHOLE -495.04,2708.05 r0 top
TP2 "TESTPOINT" TP_50MIL-25MILHOLE -693.36,2538.55 r0 top
TP3 "TESTPOINT" TP_50MIL-25MILHOLE -1423.05,2224.55 r0 top
TP4 "TESTPOINT" TP_50MIL-25MILHOLE -1237.82,952.4 r0 top
TP5 "TESTPOINT" TP_50MIL-25MILHOLE -1303.03,240.16 r0 top
TP6 "TESTPOINT" TP_50MIL-25MILHOLE -1695.54,1650.55 r0 top
TP7 "TESTPOINT" TP_50MIL-25MILHOLE -582.04,605.55 r90 top
TP8 "TESTPOINT" TP_50MIL-25MILHOLE -741.21,604.41 r90 top
U1 "TMS320F28P550SJ9PZ" PZ0100A-MFG -1150.06,2531.1 r315 top locked
U2 "MSP432E401YTPDT" PDT0128A -599.84,5050.55 r0 top locked
U3 "ISOUSB111DW" DW0016B-MFG -1437.6,4945.55 r0 top
U4 "TPD4E004DRYR" DRY0006A -1324.96,4463.74 r270 top
U5 "TPD4E004DRYR" DRY0006A -990.94,4441.73 r0 top
U6 "TS5A23157DGSR" DGS0010A_N -1325.94,3878.86 r0 top
U7 "SN74LVC2G07DBVR" DBV0006A_N -708,3737.08 r90 top
U8 "TS5A23157DGSR" DGS0010A_N -891.55,1422.07 r180 top
U9 "TS5A23157DGSR" DGS0010A_N -999.93,3854.28 r90 top
U10 "TPS3703A4330DSERQ1" DSE0006A -481.74,4206.55 r0 bottom
U11 "SN74LV4053APWR" PW0016A-MFG -1122.58,1118.27 r180 top
U13 "SN74LVC8T245PW" PW0024A-MFG -1153.31,576.85 r270 top locked
U15 "TCAN332GDR" D0008A_N -655.04,425.24 r270 top
U16 "TPD4E05U06DQAR" DQA0010A -1795.2,5112.83 r90 top
U17 "TS3A27518EPWR" PW0024A-MFG -1701.01,3085.15 r270 bottom locked
U18 "TPS61241YFFR" YFF0006AEAE -1707.51,1885.75 r0 top
U101 "TPS7A3701DRVR" DRV0006A -2085.04,4418.27 r180 top
USB101 "MUP-U22001" FP-MUP-U22001_CONN_USB_8MM94_8MM0-MFG -1819.72,5361.58 r180 top locked
Y1 "830064296" FP-830064296_SMT4_3MM4_2MM7-MFG -110.91,5152.61 r90 top
Y2 "830108207209" FP-830108207209_SMT_CRYSTAL_3MM2_2MM5-MFG -600.83,2235.37 r45 top
ZZ1 "These assemblies are ESD sensitive, ESD precautions shall be observed." AssemblyNote -2085.79,5814.55 r0 top
ZZ2 "These assemblies must be clean and free from flux and all contaminants. Use of no clean flux is not acceptable." AssemblyNote -2079.04,5960.55 r0 top
ZZ3 "These assemblies must comply with workmanship standards IPC-A-610 Class 2, unless otherwise specified." AssemblyNote -2081.71,6110.55 r0 top

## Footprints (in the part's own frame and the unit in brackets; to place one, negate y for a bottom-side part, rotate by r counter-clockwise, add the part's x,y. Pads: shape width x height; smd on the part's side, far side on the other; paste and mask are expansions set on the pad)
0402 [mm] "0402 from SM-752 data"
  rect 0.8x0.6 smd: 1(-0.6,0) 2(0.6,0)
  silkscreen extent -1.22,-0.52 1.22,0.52, body extent -0.55,-0.3 0.55,0.3, height 0.6
0603 [mm] "0603 from SM-752 data"
  rect 1x0.95 smd: 1(-0.8,0) 2(0.8,0)
  silkscreen extent -1.52,-0.69 1.52,0.69, body extent -0.87,-0.47 0.87,0.47, height 1
0805_HV [mil] "0805 with 30mil clearance between pads"
  rect 50x63 smd: 1(-40,0) 2(40,0)
  silkscreen extent -74,-40 74,40, body extent -43,-29 43,29, height 57
AssemblyNote [mil] "Assembly Note"
BoosterPack_40pin_J1J3 [mm] "Receptacle, 2.54mm, 10x2, TH"
  rrect6% 1.55x1.55 hole 1.02: 1(1.27,11.43)
  round 1.55 hole 1.02: 2(1.27,8.89) 3(1.27,6.35) 4(1.27,3.81) 5(1.27,1.27) 6(1.27,-1.27) 7(1.27,-3.81) 8(1.27,-6.35) 9(1.27,-8.89) 10(1.27,-11.43) 21(-1.27,11.43) 22(-1.27,8.89) 23(-1.27,6.35) 24(-1.27,3.81) 25(-1.27,1.27) 26(-1.27,-1.27) 27(-1.27,-3.81) 28(-1.27,-6.35) 29(-1.27,-8.89) 30(-1.27,-11.43)
  silkscreen extent -7.62,-12.95 7.62,12.95, body extent 0,0 0,0
BoosterPack_40pin_J2J4 [mm] "Receptacle, 2.54mm, 10x2, TH"
  round 1.55 hole 1.02: 11(-1.27,-11.43) 12(-1.27,-8.89) 13(-1.27,-6.35) 14(-1.27,-3.81) 15(-1.27,-1.27) 16(-1.27,1.27) 17(-1.27,3.81) 18(-1.27,6.35) 19(-1.27,8.89) 20(-1.27,11.43) 31(1.27,-11.43) 32(1.27,-8.89) 33(1.27,-6.35) 34(1.27,-3.81) 35(1.27,-1.27) 36(1.27,1.27) 37(1.27,3.81) 38(1.27,6.35) 39(1.27,8.89) 40(1.27,11.43)
  silkscreen extent -7.62,-12.95 2.48,12.95, body extent 0,0 0,0
BoosterPack_40pin_J5J7 [mm] "Receptacle, 2.54mm, 10x2, TH"
  round 1.55 hole 1.02: 41(1.27,11.43) 42(1.27,8.89) 43(1.27,6.35) 44(1.27,3.81) 45(1.27,1.27) 46(1.27,-1.27) 47(1.27,-3.81) 48(1.27,-6.35) 49(1.27,-8.89) 50(1.27,-11.43) 61(-1.27,11.43) 62(-1.27,8.89) 63(-1.27,6.35) 64(-1.27,3.81) 65(-1.27,1.27) 66(-1.27,-1.27) 67(-1.27,-3.81) 68(-1.27,-6.35) 69(-1.27,-8.89) 70(-1.27,-11.43)
  silkscreen extent -7.62,-12.95 7.62,12.95, body extent 0,0 0,0
BoosterPack_40pin_J6J8 [mm] "Receptacle, 2.54mm, 10x2, TH"
  round 1.55 hole 1.02: 51(-1.27,-11.43) 52(-1.27,-8.89) 53(-1.27,-6.35) 54(-1.27,-3.81) 55(-1.27,-1.27) 56(-1.27,1.27) 57(-1.27,3.81) 58(-1.27,6.35) 59(-1.27,8.89) 60(-1.27,11.43) 71(1.27,-11.43) 72(1.27,-8.89) 73(1.27,-6.35) 74(1.27,-3.81) 75(1.27,-1.27) 76(1.27,1.27) 77(1.27,3.81) 78(1.27,6.35) 79(1.27,8.89) 80(1.27,11.43)
  silkscreen extent -7.62,-12.95 2.48,12.95, body extent 0,0 0,0
CE_Mark_5mm [mil] "Minimum text height for CE Mark"
  silkscreen extent -138,-98 138,98
D0008A_N [mm] "SOIC, 8-Leads, Body 4.9x3.9mm, Pitch 1.27mm, IPC Medium Density"
  oval 1.45x0.6 smd: 1(-2.725,1.905) 2(-2.725,0.635) 3(-2.725,-0.635) 4(-2.725,-1.905) 5(2.725,-1.905) 6(2.725,-0.635) 7(2.725,0.635) 8(2.725,1.905)
  silkscreen extent -3.3,-2.5 0.9,2.5, body extent -3,-2.45 3,2.45, height 1.63
DBV0006A_N [mm] "SOT23, 6-Leads, Body 2.9x1.6mm, Pitch 0.95mm, Lead Span 2.8mm, IPC Medium Density"
  rrect17% 1x0.6 smd: 1(-1.375,0.95) 2(-1.375,0) 3(-1.375,-0.95) 4(1.375,-0.95) 5(1.375,0) 6(1.375,0.95)
  silkscreen extent -1.67,-1.55 0.5,1.55, body extent -1.42,-1.46 1.42,1.46, height 1.12
DGS0010A_N [mm] "TSSOP, 10-Leads, Body 3x3mm, Pitch 0.5mm, IPC Medium Density"
  oval 1.35x0.3 smd: 1(-2.225,1) 2(-2.225,0.5) 3(-2.225,0) 4(-2.225,-0.5) 5(-2.225,-1) 6(2.225,-1) 7(2.225,-0.5) 8(2.225,0) 9(2.225,0.5) 10(2.225,1)
  silkscreen extent -2.75,-1.55 0.9,1.55, body extent -2.45,-1.5 2.45,1.5, height 0.96
DQA0010A [mm] "SON, 10-Leads, Body 1x2.5mm, Pitch 0.5mm, TI Recommended"
  rrect50% 0.565x0.2 smd: 1(-0.417,1) 2(-0.418,0.5) 4(-0.418,-0.5) 5(-0.418,-1) 6(0.417,-1) 7(0.417,-0.5) 9(0.417,0.5) 10(0.417,1)
  rrect25% 0.565x0.4 smd: 3(-0.418,0) 8(0.417,0)
  rrect28% 0.565x0.36 on Top Paste: 3(-0.418,0) 8(0.417,0)
  silkscreen extent -0.67,-1.45 0.55,1.45, body extent -0.55,-1.3 0.55,1.3, height 0.56
DRV0006A [mm] "SON, 6-Leads, Body 2x2mm, Pitch 0.65mm, Thermal Pad 1.6x1mm, TI Recommended"
  rrect33% 0.45x0.3 smd: 1(-0.975,0.65) 2(-0.975,0) 3(-0.975,-0.65) 4(0.975,-0.65) 5(0.975,0) 6(0.975,0.65)
  rrect14% 1x0.7 on Top Paste: 7(0,0.45) 7(0,-0.45)
  rrect10% 1x1.6 smd: 7(0,0)
  silkscreen extent -1.05,-1.2 1.05,1.2, body extent -1.05,-1.05 1.05,1.05, height 0.81
DRY0006A [mm] "USON-6"
  rrect67% 0.45x0.3 smd: 1(-0.275,0.5)
  rrect67% 0.4x0.3 smd: 2(-0.3,0) 3(-0.3,-0.5) 4(0.3,-0.5) 5(0.3,0) 6(0.3,0.5)
  body extent -0.5,-0.72 0.5,0.73, height 0.58
DSE0006A [mm] "TI recommended land pattern"
  rect 0.66x0.25 smd: 1(-0.62,0.5)
  rect 0.7x0.25 smd: 2(-0.6,0) 3(-0.6,-0.5) 4(0.6,-0.5) 5(0.6,0) 6(0.6,0.5)
  Top Signal region: -0.3,0.625 -0.25,0.625 -0.15,0.525 -0.15,0.375 -0.3,0.375
  silkscreen extent -0.9,-0.92 0.9,0.92, body extent -0.77,-0.77 0.77,0.77, height 0.8
DW0016B-MFG [mm]
  rrect17% 1.65x0.6 smd: 1(-4.875,4.445) 2(-4.875,3.175) 3(-4.875,1.905) 4(-4.875,0.635) 5(-4.875,-0.635) 6(-4.875,-1.905) 7(-4.875,-3.175) 8(-4.875,-4.445) 9(4.875,-4.445) 10(4.875,-3.175) 11(4.875,-1.905) 12(4.875,-0.635) 13(4.875,0.635) 14(4.875,1.905) 15(4.875,3.175) 16(4.875,4.445)
  silkscreen extent -6.37,-5.25 3.5,5.25, body extent -5.8,-5.5 5.8,5.5, height 0.25
FCC_disclaimer [mil]
Fiducial10-20 [mm]
  round 1 smd mask+0.5: 1(0,0)
  Top Signal keep-out circle w1.178: c0,0 r0.5
FP-830064296_SMT4_3MM4_2MM7-MFG [mm]
  rrect9% 1.4x1.15 smd paste+0 mask+0: 1(-1.1,-0.8) 2(1.1,-0.8) 3(1.1,0.8) 4(-1.1,0.8)
  silkscreen extent -2.17,-2.05 2.17,1.35, body extent -1.9,-1.48 1.9,1.48, height 0.25
FP-61300421121_HDR4-MFG#1 [mm]
  rrect6% 1.7x1.7 hole 1.1: 1(-1.27,1.27)
  round 1.7 hole 1.1: 2(-1.27,-1.27) 3(1.27,1.27) 4(1.27,-1.27)
  silkscreen extent -2.69,-2.62 2.69,3.22, body extent -2.54,-2.54 2.54,2.54, height 8.89
FP-61300421121_HDR4-MFG#2 [mm]
  rrect6% 1.7x1.7 hole 1.1 paste-1000 mask+0: 1(-1.27,-1.27)
  round 1.7 hole 1.1 paste-1000 mask+0: 2(-1.27,1.27) 3(1.27,-1.27) 4(1.27,1.27)
  silkscreen extent -2.69,-3.22 2.69,2.62, body extent -2.79,-2.72 2.79,2.72, height 0.25
FP-61301221121_HDR12-MFG [mm]
  rrect6% 1.7x1.7 hole 1.1: 1(-6.35,-1.27)
  round 1.7 hole 1.1: 2(-6.35,1.27) 3(-3.81,-1.27) 4(-3.81,1.27) 5(-1.27,-1.27) 6(-1.27,1.27) 7(1.27,-1.27) 8(1.27,1.27) 9(3.81,-1.27) 10(3.81,1.27) 11(6.35,-1.27) 12(6.35,1.27)
  silkscreen extent -7.77,-3.22 7.77,2.62, body extent -7.87,-2.72 7.87,2.72, height 0.25
FP-830108207209_SMT_CRYSTAL_3MM2_2MM5-MFG [mm]
  rrect9% 1.4x1.15 smd paste+0 mask+0: 1(-1.1,-0.8) 2(1.1,-0.8) 3(1.1,0.8) 4(-1.1,0.8)
  silkscreen extent -1.22,-2.05 0,1.35, body extent -1.9,-1.47 1.9,1.47, height 0.25
FP-885012205018_0402-MFG [mm]
  rrect20% 0.5x0.5 smd paste+0 mask+0: 1(-0.5,0) 2(0.5,0)
  silkscreen extent -0.5,-0.63 0.5,0.63, body extent -0.85,-0.38 0.85,0.38, height 0.25
FP-885012205050_0402-MFG [mm]
  rrect20% 0.5x0.5 smd paste+0 mask+0: 1(-0.5,0) 2(0.5,0)
  silkscreen extent -0.53,-0.63 0.53,0.63, body extent -0.85,-0.38 0.85,0.38, height 0.25
FP-885012205064_0402-MFG [mm]
  rrect20% 0.5x0.5 smd paste+0 mask+0: 1(-0.5,0) 2(0.5,0)
  silkscreen extent -0.53,-0.63 0.53,0.63, body extent -0.85,-0.38 0.85,0.38, height 0.25
FP-CC0603KRX5R6BB106_0603-MFG [mm]
  rrect13% 0.8x0.9 smd paste+0 mask+0: 1(-0.75,0) 2(0.75,0)
  silkscreen extent -0.85,-0.88 0.85,0.88, body extent -0.8,-0.4 0.8,0.4, height 1
FP-FTSH-107-01-F-DV-K_HDR14-MFG [mm]
  rrect14% 0.74x2.79 smd: 1(-3.81,-2.035) 2(-3.81,2.035) 3(-2.54,-2.035) 4(-2.54,2.035) 5(-1.27,-2.035) 6(-1.27,2.035) 7(0,-2.035) 8(0,2.035) 9(1.27,-2.035) 10(1.27,2.035) 11(2.54,-2.035) 12(2.54,2.035) 13(3.81,-2.035) 14(3.81,2.035)
  silkscreen extent -4.51,-4.11 4.51,0.27, body extent -4.61,-3.53 4.61,3.53, height 0.25
FP-MUP-U22001_CONN_USB_8MM94_8MM0-MFG [mm]
  rrect100% 0.6x1.9 hole 1.9 slot 0.6 at 0 deg: 1(-4.32,3.35) 2(4.32,3.35)
  round 1.207 smd: 1(-4.25,2.92) 2(4.25,2.92)
  round 1.207 smd far side: 1(-4.25,2.92) 2(4.25,2.92)
  rrect100% 1.25x0.7 hole 0.7 slot 1.25 at 0 deg: 1(-3.995,2.75) 2(3.995,2.75)
  rrect100% 0.7x1.5 hole 1.5 slot 0.7 at 0 deg: 3(-5.85,-1.95) 4(5.85,-1.95)
  round 1.17 smd far side: 3(-5.85,-1.625) 4(5.85,-1.625)
  round 1.17 smd: 3(-5.85,-1.625) 4(5.85,-1.625)
  rrect37% 0.27x0.9 smd: A1(-2.625,4.05) A2(-2.125,4.05) A3(-1.625,4.05) A4(-1.125,4.05) A5(-0.625,4.05) A6(-0.125,4.05) A7(0.375,4.05) A8(0.875,4.05) A9(1.375,4.05) A10(1.875,4.05) A11(2.375,4.05) A12(2.875,4.05)
  rrect37% 0.27x0.8 smd: B1(2.625,2.45) B2(2.125,2.45) B3(1.625,2.45) B4(1.125,2.45) B5(0.625,2.45) B6(0.125,2.45) B7(-0.375,2.45) B8(-0.875,2.45) B9(-1.375,2.45) B10(-1.875,2.45) B11(-2.375,2.45) B12(-2.875,2.45)
  Top Signal region: 3.72,3.35 3.72,4.05 3.72,4.169 3.811,4.39 3.98,4.559 4.201,4.65 4.32,4.65 4.439,4.65 4.66,4.559 4.829,4.39 4.92,4.169 4.92,4.05 4.92,2.85 4.92,2.731 4.829,2.51 4.66,2.341 4.439,2.25 4.32,2.25 3.82,2.25 3.711,2.25 3.508,2.334 3.354,2.488 3.27,2.691 3.27,2.8 3.268,2.898 3.332,3.082 3.456,3.233 3.624,3.332
  Top Signal region: 6.5,-2.349 6.5,-2.472 6.411,-2.701 6.244,-2.882 6.023,-2.99 5.9,-2.999 5.833,-3.004 5.699,-2.987 5.572,-2.942 5.457,-2.873 5.358,-2.781 5.281,-2.672 5.227,-2.548 5.2,-2.416 5.2,-2.349 5.2,-0.749 5.2,-0.65 5.276,-0.466 5.417,-0.325 5.601,-0.249 5.7,-0.249 6,-0.249 6.099,-0.249 6.283,-0.325 6.424,-0.466 6.5,-0.65 6.5,-0.749
  Top Signal region: -3.72,3.35 -3.72,4.05 -3.72,4.169 -3.811,4.39 -3.98,4.559 -4.201,4.65 -4.439,4.65 -4.66,4.559 -4.829,4.39 -4.92,4.169 -4.92,4.05 -4.92,2.85 -4.92,2.731 -4.829,2.51 -4.66,2.341 -4.439,2.25 -4.32,2.25 -3.711,2.25 -3.508,2.334 -3.354,2.488 -3.27,2.691 -3.27,2.8 -3.268,2.898 -3.332,3.082 -3.456,3.233 -3.624,3.332
  Top Signal region: -6.5,-2.349 -6.5,-2.472 -6.411,-2.701 -6.244,-2.882 -6.023,-2.99 -5.9,-2.999 -5.833,-3.004 -5.699,-2.987 -5.572,-2.942 -5.457,-2.873 -5.358,-2.781 -5.281,-2.672 -5.227,-2.548 -5.2,-2.416 -5.2,-2.349 -5.2,-0.749 -5.2,-0.65 -5.276,-0.466 -5.417,-0.325 -5.601,-0.249 -5.7,-0.249 -6,-0.249 -6.099,-0.249 -6.283,-0.325 -6.424,-0.466 -6.5,-0.65 -6.5,-0.749
  Bottom Signal region: 3.72,3.35 3.72,4.05 3.72,4.169 3.811,4.39 3.98,4.559 4.201,4.65 4.32,4.65 4.439,4.65 4.66,4.559 4.829,4.39 4.92,4.169 4.92,4.05 4.92,2.85 4.92,2.731 4.829,2.51 4.66,2.341 4.439,2.25 4.32,2.25 3.82,2.25 3.711,2.25 3.508,2.334 3.354,2.488 3.27,2.691 3.27,2.8 3.268,2.898 3.332,3.082 3.456,3.233 3.624,3.332
  Bottom Signal region: -3.72,3.35 -3.72,4.05 -3.72,4.169 -3.811,4.39 -3.98,4.559 -4.201,4.65 -4.32,4.65 -4.439,4.65 -4.66,4.559 -4.829,4.39 -4.92,4.169 -4.92,4.05 -4.92,2.85 -4.92,2.731 -4.829,2.51 -4.66,2.341 -4.439,2.25 -4.32,2.25 -3.82,2.25 -3.711,2.25 -3.508,2.334 -3.354,2.488 -3.27,2.691 -3.27,2.8 -3.268,2.898 -3.332,3.082 -3.456,3.233 -3.624,3.332
  Bottom Signal region: 6.5,-2.349 6.5,-2.472 6.411,-2.701 6.244,-2.882 6.023,-2.99 5.9,-2.999 5.833,-3.004 5.699,-2.987 5.572,-2.942 5.457,-2.873 5.358,-2.781 5.281,-2.672 5.227,-2.548 5.2,-2.416 5.2,-2.349 5.2,-0.749 5.2,-0.65 5.276,-0.466 5.417,-0.325 5.601,-0.249 5.7,-0.249 6,-0.249 6.099,-0.249 6.283,-0.325 6.424,-0.466 6.5,-0.65 6.5,-0.749
  Bottom Signal region: -6.5,-2.349 -6.5,-2.472 -6.411,-2.701 -6.244,-2.882 -6.023,-2.99 -5.9,-2.999 -5.833,-3.004 -5.699,-2.987 -5.572,-2.942 -5.457,-2.873 -5.358,-2.781 -5.281,-2.672 -5.227,-2.548 -5.2,-2.416 -5.2,-2.349 -5.2,-0.749 -5.2,-0.65 -5.276,-0.466 -5.417,-0.325 -5.601,-0.249 -5.7,-0.249 -6,-0.249 -6.099,-0.249 -6.283,-0.325 -6.424,-0.466 -6.5,-0.65 -6.5,-0.749
  Keep-Out Layer lines w0.2: 4.7,-3.5 4.7,0.75 ccw(c4.7,1.25) 5.2,1.25 ccw(c4.7,1.25) 4.7,1.75 -4.7,1.75 ccw(c-4.7,1.25) -5.2,1.25 ccw(c-4.7,1.25) -4.7,0.75 -4.7,-3.5
  silkscreen extent -6,0.13 6,5.17, body extent -6.6,-4.23 6.6,4.75, height 0.25
FP-TSW-103-07-G-T_HDR9-MFG [mm]
  rrect6% 1.57x1.57 hole 1.02 paste-1000 mask+0: 1(-2.54,-2.54)
  round 1.57 hole 1.02 paste-1000 mask+0: 2(-2.54,0) 3(-2.54,2.54) 4(0,-2.54) 5(0,0) 6(0,2.54) 7(2.54,-2.54) 8(2.54,0) 9(2.54,2.54)
  silkscreen extent -4.66,-3.88 3.94,3.88, body extent -4.04,-3.98 4.04,3.98, height 0.25
LED_LTST-C171 [mm] "LITE-ON"
  rect 1.2x1.2 smd: 1(-1.05,0) 2(1.05,0)
  silkscreen extent -1.6,-1 2.2,1, body extent -1.05,-0.67 1.05,0.67, height 0.8
LTST-C170TBKT_Blue [mm] "LITE-ON"
  rect 1.2x1.2 smd: 1(-1.05,0) 2(1.05,0)
  silkscreen extent -1.6,-1 2.2,1, body extent -1.05,-0.67 1.05,0.67, height 1.2
NPTH125mil [mil]
  round 120 hole 125 unplated: 1(0,0)
PDT0128A [mm] "Thin QFP, 128-Leads, Body 14x14mm, Pitch 0.4mm"
  oval 1.4x0.2 smd: 1(-7.7,6.2) 2(-7.7,5.8) 3(-7.7,5.4) 4(-7.7,5) 5(-7.7,4.6) 6(-7.7,4.2) 7(-7.7,3.8) 8(-7.7,3.4) 9(-7.7,3) 10(-7.7,2.6) 11(-7.7,2.2) 12(-7.7,1.8) 13(-7.7,1.4) 14(-7.7,1) 15(-7.7,0.6) 16(-7.7,0.2) 17(-7.7,-0.2) 18(-7.7,-0.6) 19(-7.7,-1) 20(-7.7,-1.4) 21(-7.7,-1.8) 22(-7.7,-2.2) 23(-7.7,-2.6) 24(-7.7,-3) 25(-7.7,-3.4) 26(-7.7,-3.8) 27(-7.7,-4.2) 28(-7.7,-4.6) 29(-7.7,-5) 30(-7.7,-5.4) 31(-7.7,-5.8) 32(-7.7,-6.2) 65(7.7,-6.2) 66(7.7,-5.8) 67(7.7,-5.4) 68(7.7,-5) 69(7.7,-4.6) 70(7.7,-4.2) 71(7.7,-3.8) 72(7.7,-3.4) 73(7.7,-3) 74(7.7,-2.6) 75(7.7,-2.2) 76(7.7,-1.8) 77(7.7,-1.4) 78(7.7,-1) 79(7.7,-0.6) 80(7.7,-0.2) 81(7.7,0.2) 82(7.7,0.6) 83(7.7,1) 84(7.7,1.4) 85(7.7,1.8) 86(7.7,2.2) 87(7.7,2.6) 88(7.7,3) 89(7.7,3.4) 90(7.7,3.8) 91(7.7,4.2) 92(7.7,4.6) 93(7.7,5) 94(7.7,5.4) 95(7.7,5.8) 96(7.7,6.2)
  oval 0.2x1.4 smd: 33(-6.2,-7.7) 34(-5.8,-7.7) 35(-5.4,-7.7) 36(-5,-7.7) 37(-4.6,-7.7) 38(-4.2,-7.7) 39(-3.8,-7.7) 40(-3.4,-7.7) 41(-3,-7.7) 42(-2.6,-7.7) 43(-2.2,-7.7) 44(-1.8,-7.7) 45(-1.4,-7.7) 46(-1,-7.7) 47(-0.6,-7.7) 48(-0.2,-7.7) 49(0.2,-7.7) 50(0.6,-7.7) 51(1,-7.7) 52(1.4,-7.7) 53(1.8,-7.7) 54(2.2,-7.7) 55(2.6,-7.7) 56(3,-7.7) 57(3.4,-7.7) 58(3.8,-7.7) 59(4.2,-7.7) 60(4.6,-7.7) 61(5,-7.7) 62(5.4,-7.7) 63(5.8,-7.7) 64(6.2,-7.7) 97(6.2,7.7) 98(5.8,7.7) 99(5.4,7.7) 100(5,7.7) 101(4.6,7.7) 102(4.2,7.7) 103(3.8,7.7) 104(3.4,7.7) 105(3,7.7) 106(2.6,7.7) 107(2.2,7.7) 108(1.8,7.7) 109(1.4,7.7) 110(1,7.7) 111(0.6,7.7) 112(0.2,7.7) 113(-0.2,7.7) 114(-0.6,7.7) 115(-1,7.7) 116(-1.4,7.7) 117(-1.8,7.7) 118(-2.2,7.7) 119(-2.6,7.7) 120(-3,7.7) 121(-3.4,7.7) 122(-3.8,7.7) 123(-4.2,7.7) 124(-4.6,7.7) 125(-5,7.7) 126(-5.4,7.7) 127(-5.8,7.7) 128(-6.2,7.7)
  silkscreen extent -7.7,-6.3 6.3,6.99, body extent -8,-8 8,8, height 1.07
PW0016A-MFG [mm]
  rrect22% 1.5x0.45 smd: 1(-2.9,2.275) 2(-2.9,1.625) 3(-2.9,0.975) 4(-2.9,0.325) 5(-2.9,-0.325) 6(-2.9,-0.975) 7(-2.9,-1.625) 8(-2.9,-2.275) 9(2.9,-2.275) 10(2.9,-1.625) 11(2.9,-0.975) 12(2.9,-0.325) 13(2.9,0.325) 14(2.9,0.975) 15(2.9,1.625) 16(2.9,2.275)
  silkscreen extent -4.38,-2.55 1.78,2.55, body extent -3.75,-2.8 3.75,2.8, height 0.25
PW0024A-MFG [mm]
  rrect22% 1.5x0.45 smd paste+0 mask+0: 1(-2.9,3.575) 2(-2.9,2.925) 3(-2.9,2.275) 4(-2.9,1.625) 5(-2.9,0.975) 6(-2.9,0.325) 7(-2.9,-0.325) 8(-2.9,-0.975) 9(-2.9,-1.625) 10(-2.9,-2.275) 11(-2.9,-2.925) 12(-2.9,-3.575) 13(2.9,-3.575) 14(2.9,-2.925) 15(2.9,-2.275) 16(2.9,-1.625) 17(2.9,-0.975) 18(2.9,-0.325) 19(2.9,0.325) 20(2.9,0.975) 21(2.9,1.625) 22(2.9,2.275) 23(2.9,2.925) 24(2.9,3.575)
  silkscreen extent -4.32,-3.95 1.78,3.95, body extent -3.75,-4.2 3.75,4.2, height 0.25
PZ0100A-MFG [mm]
  rrect33% 1.6x0.3 smd paste-1000 mask+0: 1(-7.6,6) 2(-7.6,5.5) 3(-7.6,5) 4(-7.6,4.5) 5(-7.6,4) 6(-7.6,3.5) 7(-7.6,3) 8(-7.6,2.5) 9(-7.6,2) 10(-7.6,1.5) 11(-7.6,1) 12(-7.6,0.5) 13(-7.6,0) 14(-7.6,-0.5) 15(-7.6,-1) 16(-7.6,-1.5) 17(-7.6,-2) 18(-7.6,-2.5) 19(-7.6,-3) 20(-7.6,-3.5) 21(-7.6,-4) 22(-7.6,-4.5) 23(-7.6,-5) 24(-7.6,-5.5) 25(-7.6,-6) 51(7.6,-6) 52(7.6,-5.5) 53(7.6,-5) 54(7.6,-4.5) 55(7.6,-4) 56(7.6,-3.5) 57(7.6,-3) 58(7.6,-2.5) 59(7.6,-2) 60(7.6,-1.5) 61(7.6,-1) 62(7.6,-0.5) 63(7.6,0) 64(7.6,0.5) 65(7.6,1) 66(7.6,1.5) 67(7.6,2) 68(7.6,2.5) 69(7.6,3) 70(7.6,3.5) 71(7.6,4) 72(7.6,4.5) 73(7.6,5) 74(7.6,5.5) 75(7.6,6)
  rrect33% 0.3x1.6 smd paste-1000 mask+0: 26(-6,-7.6) 27(-5.5,-7.6) 28(-5,-7.6) 29(-4.5,-7.6) 30(-4,-7.6) 31(-3.5,-7.6) 32(-3,-7.6) 33(-2.5,-7.6) 34(-2,-7.6) 35(-1.5,-7.6) 36(-1,-7.6) 37(-0.5,-7.6) 38(0,-7.6) 39(0.5,-7.6) 40(1,-7.6) 41(1.5,-7.6) 42(2,-7.6) 43(2.5,-7.6) 44(3,-7.6) 45(3.5,-7.6) 46(4,-7.6) 47(4.5,-7.6) 48(5,-7.6) 49(5.5,-7.6) 50(6,-7.6) 76(6,7.6) 77(5.5,7.6) 78(5,7.6) 79(4.5,7.6) 80(4,7.6) 81(3.5,7.6) 82(3,7.6) 83(2.5,7.6) 84(2,7.6) 85(1.5,7.6) 86(1,7.6) 87(0.5,7.6) 88(0,7.6) 89(-0.5,7.6) 90(-1,7.6) 91(-1.5,7.6) 92(-2,7.6) 93(-2.5,7.6) 94(-3,7.6) 95(-3.5,7.6) 96(-4,7.6) 97(-4.5,7.6) 98(-5,7.6) 99(-5.5,7.6) 100(-6,7.6)
  silkscreen extent -9.12,-7.1 7.1,7.1, body extent -8.5,-8.5 8.5,8.5, height 0.25
Samtec_TSM-102-01-x-DV [mil] "Header, 2.54mm, 2x2, SMT"
  rect 120x50 smd: 1(-97.44,-50) 2(97.44,-50) 3(-97.44,50) 4(97.44,50)
  silkscreen extent -69,-104 65,100, body extent -151,-100 152,100, height 380
SW_1188E [mm] "SMD, 4-Leads, Body 7.8x3.5mm"
  rrect10% 1x1.45 smd: 1(-1.1,3.375) 2(-1.1,-3.375)
  rrect11% 1.3x0.9 smd: 3(0.7,2.1) 4(0.7,-2.1)
  round 0 hole 0.9 unplated: ""(-0.35,1.15) ""(-0.35,-1.15)
  silkscreen extent -1.98,-2.28 0.95,2.28, body extent -2.55,-3.9 1.05,3.9, height 3.5
SW_CAS-120TA [mm] "COPAL ELECTRONICS"
  rect 1.6x1 smd: 1(-1.15,1.75) 2(1.15,0) 3(-1.15,-1.75)
  silkscreen extent -2,-2.85 1.4,2.92, body extent -1.4,-2.85 1.4,2.85, height 2.51
SW_CAS-220TA [mm] "COPAL ELECTRONICS"
  rect 1.6x1 smd: 1(-1.85,1.75) 2(-1.85,0) 3(-1.85,-1.75) 4(1.85,1.75) 5(1.85,0) 6(1.85,-1.75)
  silkscreen extent -2.11,-2.9 2,3.58, body extent -2.1,-2.85 2.1,2.85, height 2.51
SW_CAS-D20TA [mm] "SMD, 6-Leads, Body 5.4x3.9mm, Pitch 1.75mm"
  rect 1.6x1 smd: 1(-1.85,1.75) 2(-1.85,0) 3(-1.85,-1.75) 4(1.85,1.75) 5(1.85,0) 6(1.85,-1.75)
  silkscreen extent -1.95,-2.7 1.95,2.9, body extent -2.1,-2.7 2.1,2.7, height 2.5
TI_Stacked_Overlay_Medium [mil]
  silkscreen extent -576,-136 576,135
TI_Symbol_Overlay_Small [mil]
  silkscreen extent -90,-88 91,88
TP_50MIL-25MILHOLE [mil]
  round 50 hole 25: 1(0,0)
WEEE_Minimum [mil] "WEEElie bin"
  silkscreen extent -95,-172 99,104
